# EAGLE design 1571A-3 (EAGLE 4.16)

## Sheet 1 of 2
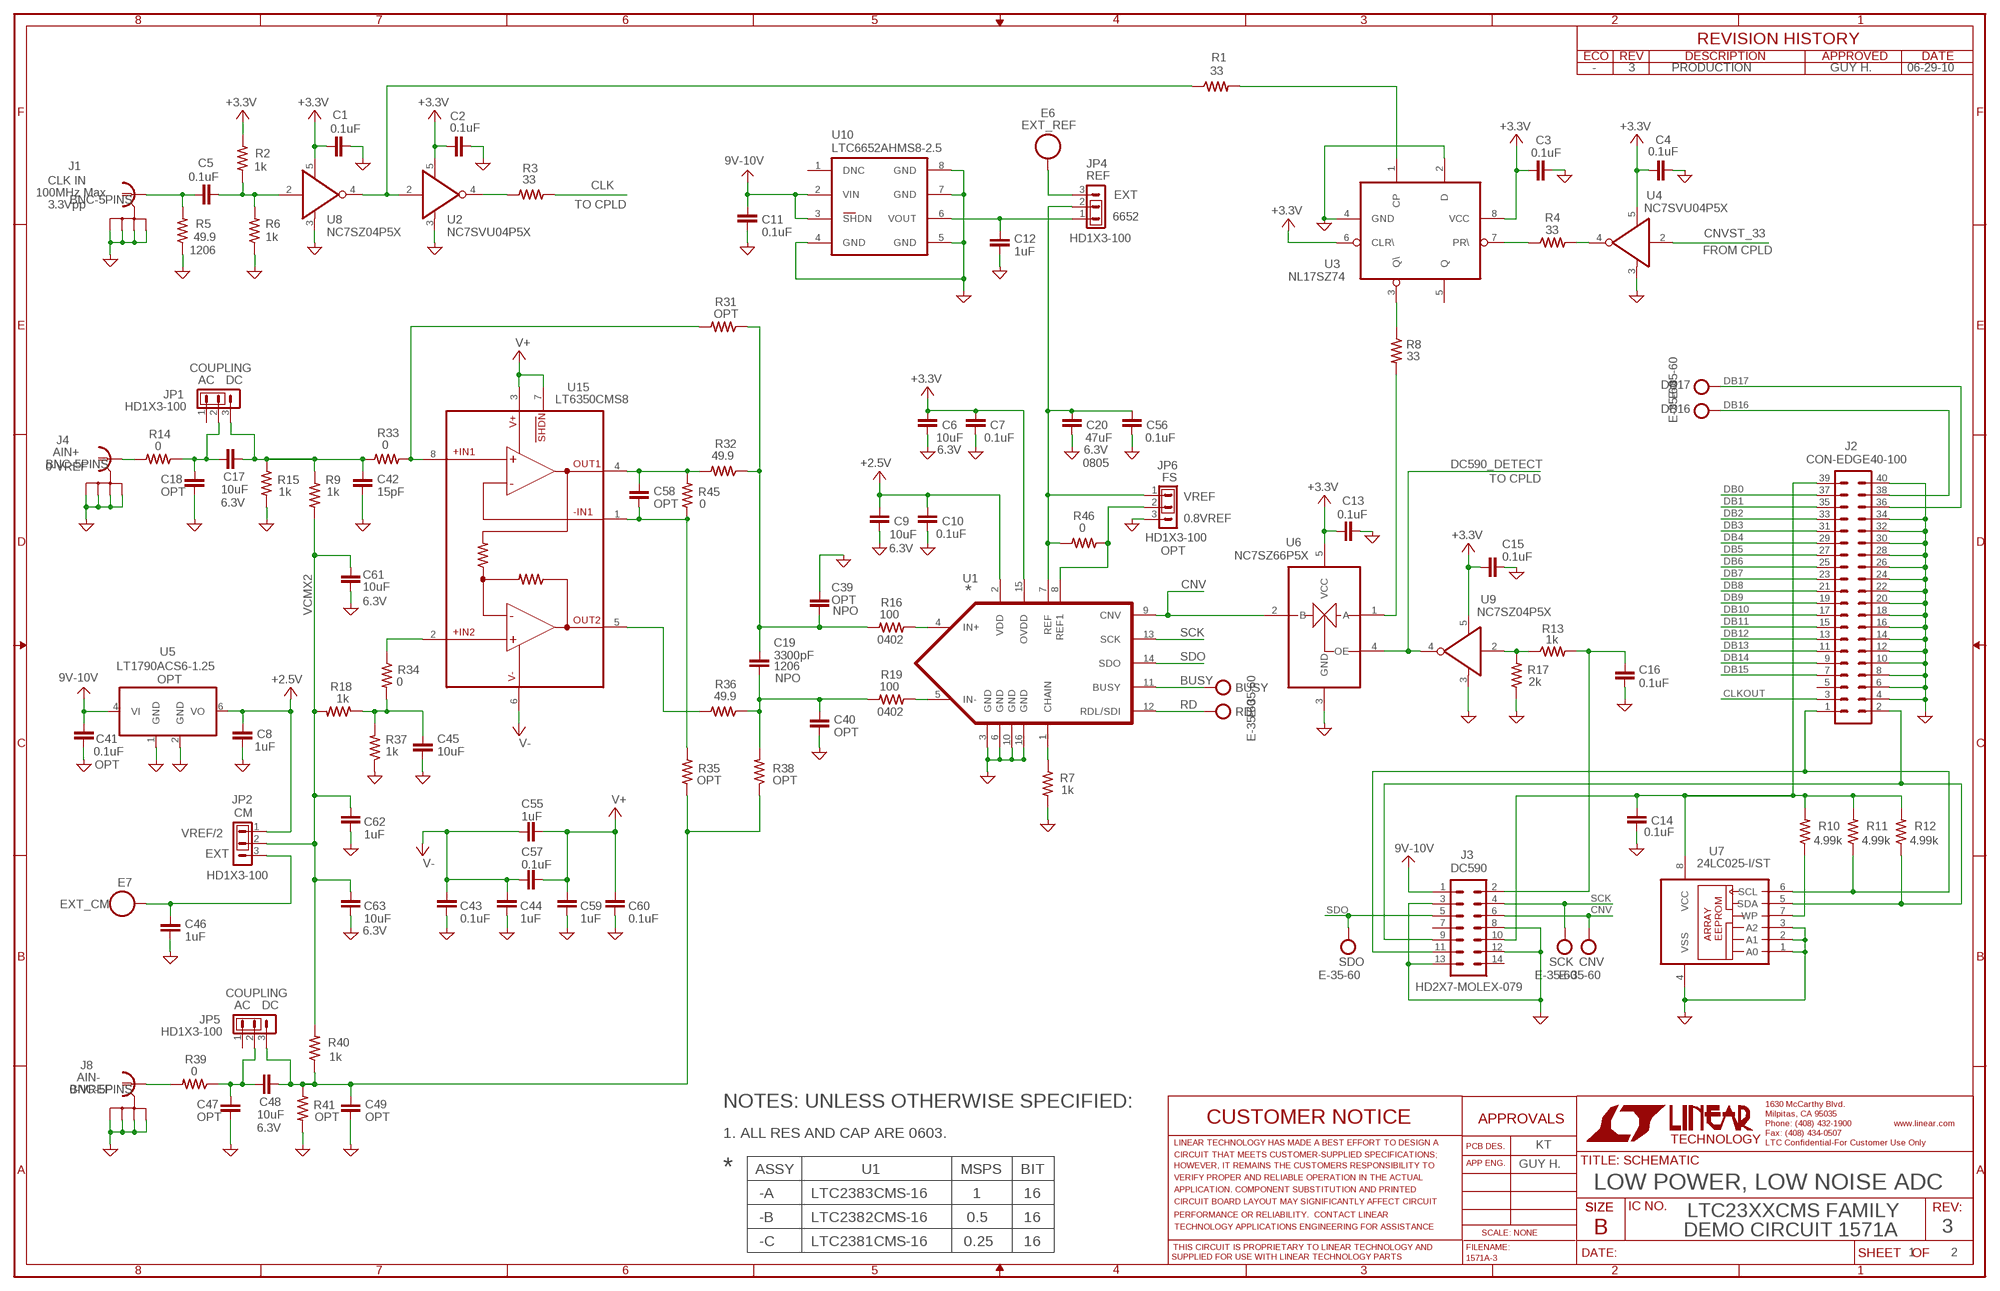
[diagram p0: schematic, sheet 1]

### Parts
BUSY  E-35-60  [PAD-35-60]
C1  0.1uF  CAP-NP-SMT-0603  [0603]
C2  0.1uF  CAP-NP-SMT-0603  [0603]
C3  0.1uF  CAP-NP-SMT-0603  [0603]
C4  0.1uF  CAP-NP-SMT-0603  [0603]
C5  0.1uF  CAP-NP-SMT-0603  [0603]
C6  10uF  CAP-NP-SMT-0603  [0603]
C7  0.1uF  CAP-NP-SMT-0603  [0603]
C8  1uF  CAP-NP-SMT-0603  [0603]
C9  10uF  CAP-NP-SMT-0603  [0603]
C10  0.1uF  CAP-NP-SMT-0603  [0603]
C11  0.1uF  CAP-NP-SMT-0603  [0603]
C12  1uF  CAP-NP-SMT-0603  [0603]
C13  0.1uF  CAP-NP-SMT-0603  [0603]
C14  0.1uF  CAP-NP-SMT-0603  [0603]
C15  0.1uF  CAP-NP-SMT-0603  [0603]
C16  0.1uF  CAP-NP-SMT-0603  [0603]
C17  10uF  CAP-NP-SMT-0603  [0603]
C18  OPT  CAP-NP-SMT-0603  [0603]
C19  3300pF  CAP-NP-SMT-1206  [1206]
C20  47uF  CAP-NP-SMT-0805  [0805]
C39  OPT  CAP-NP-SMT-0603  [0603]
C40  OPT  CAP-NP-SMT-0603  [0603]
C41  0.1uF  CAP-NP-SMT-0603  [0603]
C42  15pF  CAP-NP-SMT-0603  [0603]
C43  0.1uF  CAP-NP-SMT-0603  [0603]
C44  1uF  CAP-NP-SMT-0603  [0603]
C45  10uF  CAP-NP-SMT-0603  [0603]
C46  1uF  CAP-NP-SMT-0603  [0603]
C47  OPT  CAP-NP-SMT-0603  [0603]
C48  10uF  CAP-NP-SMT-0603  [0603]
C49  OPT  CAP-NP-SMT-0603  [0603]
C55  1uF  CAP-NP-SMT-0603  [0603]
C56  0.1uF  CAP-NP-SMT-0603  [0603]
C57  0.1uF  CAP-NP-SMT-0603  [0603]
C58  OPT  CAP-NP-SMT-0603  [0603]
C59  1uF  CAP-NP-SMT-0603  [0603]
C60  0.1uF  CAP-NP-SMT-0603  [0603]
C61  10uF  CAP-NP-SMT-0603  [0603]
C62  1uF  CAP-NP-SMT-0603  [0603]
C63  10uF  CAP-NP-SMT-0603  [0603]
CNV  E-35-60  [PAD-35-60]
DB16  E-35-60  [PAD-35-60]
DB17  E-35-60  [PAD-35-60]
E6  EXT_REF  TP-94-2501-2  [MILLMAX-2501-2]
E7  EXT_CM  TP-94-2501-2  [MILLMAX-2501-2]
J1  BNC-5PINS  [BNC-112404]
J2  CON-EDGE40-100  [CON-EDGE40-100]
J3  HD2X7-MOLEX-079  [HD2X7-079-MOLEX]
J4  BNC-5PINS  [BNC-112404]
J8  BNC-5PINS  [BNC-112404]
JP1  HD1X3-100  [HD1X3-100]
JP2  HD1X3-100  [HD1X3-100]
JP4  HD1X3-100  [HD1X3-100]
JP5  HD1X3-100  [HD1X3-100]
JP6  OPT  HD1X3-100  [HD1X3-100]
R1  33  RES-0603  [0603]
R2  1k  RES-0603  [0603]
R3  33  RES-0603  [0603]
R4  33  RES-0603  [0603]
R5  49.9  RES-1206  [1206]
R6  1k  RES-0603  [0603]
R7  1k  RES-0603  [0603]
R8  33  RES-0603  [0603]
R9  1k  RES-0603  [0603]
R10  4.99k  RES-0603  [0603]
R11  4.99k  RES-0603  [0603]
R12  4.99k  RES-0603  [0603]
R13  1k  RES-0603  [0603]
R14  0  RES-0603  [0603]
R15  1k  RES-0603  [0603]
R16  100  RES-0402  [0402]
R17  2k  RES-0603  [0603]
R18  1k  RES-0603  [0603]
R19  100  RES-0402  [0402]
R31  OPT  RES-0603  [0603]
R32  49.9  RES-0603  [0603]
R33  0  RES-0603  [0603]
R34  0  RES-0603  [0603]
R35  OPT  RES-0603  [0603]
R36  49.9  RES-0603  [0603]
R37  1k  RES-0603  [0603]
R38  OPT  RES-0603  [0603]
R39  0  RES-0603  [0603]
R40  1k  RES-0603  [0603]
R41  OPT  RES-0603  [0603]
R45  0  RES-0603  [0603]
R46  0  RES-0603  [0603]
RD  E-35-60  [PAD-35-60]
SCK  E-35-60  [PAD-35-60]
SDO  E-35-60  [PAD-35-60]
U1  *  LTC238X-16PINS  [MS16]
U2  NC7SVU04P5X  [SC70-5]
U3  NL17SZ74  [US8]
U4  NC7SVU04P5X  NC7ST04P5X  [SC70-5]
U5  LT1790ACS6-1.25  LT1790ACS6-2.048  [SOT23-6]
U6  NC7SZ66P5X  [SC70-5]
U7  24LC025-I/ST  [TSSOP8]
U8  NC7SZ04P5X  [SC70-5]
U9  NC7SZ04P5X  [SC70-5]
U10  LTC6652AHMS8-2.5  [MS8]
U15  LT6350CMS8  [MS8]

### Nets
9V-10V: C11.2 C41.2 J3.1 U5.4(VI) U10.2(VIN) U10.3(SHDN) ; also sheet 2
+2.5V: C8.2 C9.2 C10.2 JP2.1 U1.2(VDD) U5.6(VO) ; also sheet 2
+3.3V: C1.1 C2.1 C3.1 C4.1 C6.2 C7.2 C13.1 C15.2 R2.2 U1.15(OVDD) U2.5(VCC) U3.6(CLR\) U3.8(VCC) U4.5(VCC) U6.5(VCC) U8.5(VCC) U9.5(VCC) ; also sheet 2
BUSY: BUSY.1 U1.11(BUSY) ; also sheet 2
CLK: R3.2 ; also sheet 2
CLKOUT: J2.3 ; also sheet 2
CNV: CNV.1 J3.6 U1.9(CNV) U6.2(B)
CNVST_33: U4.2(A) ; also sheet 2
DB0: J2.37 ; also sheet 2
DB1: J2.35 ; also sheet 2
DB2: J2.33 ; also sheet 2
DB3: J2.31 ; also sheet 2
DB4: J2.29 ; also sheet 2
DB5: J2.27 ; also sheet 2
DB6: J2.25 ; also sheet 2
DB7: J2.23 ; also sheet 2
DB8: J2.21 ; also sheet 2
DB9: J2.19 ; also sheet 2
DB10: J2.17 ; also sheet 2
DB11: J2.15 ; also sheet 2
DB12: J2.13 ; also sheet 2
DB13: J2.11 ; also sheet 2
DB14: J2.9 ; also sheet 2
DB15: J2.7 ; also sheet 2
DB16: DB16.1 J2.38 ; also sheet 2
DB17: DB17.1 J2.36 ; also sheet 2
DC590_DETECT: U6.4(OE) U9.4(Y) ; also sheet 2
DC590VP: C16.1 J3.2 R13.2
GND: C1.2 C2.2 C3.2 C4.2 C6.1 C7.1 C8.1 C9.1 C10.1 C11.1 C12.1 C13.2 C14.2 C15.1 C16.2 C18.2 C20.1 C39.2 C40.2 C41.1 C42.2 C43.2 C44.2 C45.1 C46.1 C47.2 C49.2 C56.1 C59.2 C60.2 C61.2 C62.2 C63.2 J1.2(GND) J1.3(GND) J1.4(GND) J1.5(GND) J2.4 J2.6 J2.8 J2.10 J2.12 J2.14 J2.16 J2.18 J2.20 J2.22 J2.24 J2.26 J2.28 J2.30 J2.32 J2.34 J2.40 J3.3 J3.8 J3.12 J3.13 J4.2(GND) J4.3(GND) J4.4(GND) J4.5(GND) J8.2(GND) J8.3(GND) J8.4(GND) J8.5(GND) JP6.3 R5.1 R6.1 R7.2 R15.2 R17.1 R37.1 R41.2 U1.3(GND) U1.6(GND) U1.10(GND) U1.16(GND) U2.3(GND) U3.2(D) U3.4(GND) U4.3(GND) U5.1(GND) U5.2(GND) U6.3(GND) U7.1(A0) U7.2(A1) U7.3(A2) U7.4(VSS) U8.3(GND) U9.3(GND) U10.4(GND) U10.5(GND) U10.7(GND) U10.8(GND) ; supply symbol labelled - ; also sheet 2
N$1: C17.1 C18.1 JP1.2 R14.1
N$2: J4.1 R14.2
N$7: C20.2 C56.2 JP4.2 JP6.1 R46.1 U1.7(REF)
N$8: C58.1 R32.2 R45.1 U15.4(OUT1)
N$10: E6.1 JP4.3
N$11: R7.1 U1.1(CHAIN)
N$12: R8.1 U3.3(Q\)
N$13: R13.1 R17.2 U9.2(A)
N$15: R16.1 U1.4(IN+)
N$16: R19.1 U1.5(IN-)
N$17: R10.1 U7.7(WP)
N$19: J2.1 J3.11 R11.1 U7.6(SCL)
N$21: C12.2 JP4.1 U10.6(VOUT)
N$22: C19.1 C39.1 R16.2 R31.1 R32.1
N$23: R4.1 U3.7(PR\)
N$24: C46.2 E7.1 JP2.3
N$25: R4.2 U4.4(Y)
N$26: C17.2 C42.1 JP1.3 R9.1 R15.1 R33.2
N$27: C5.1 J1.1 R5.2
N$28: C5.2 R2.1 R6.2 U8.2(A)
N$29: R1.2 U3.1(CP)
N$31: R3.1 U2.4(Y)
N$32: C19.2 C40.1 R19.2 R36.1 R38.2
N$33: R31.2 R33.1 U15.8(+IN1)
N$34: J2.2 J3.9 R12.1 U7.5(SDA)
N$36: R1.1 U2.2(A) U8.4(Y)
N$37: C45.2 R18.1 R34.2 R37.2
N$39: JP6.2 R46.2 U1.8(REF1)
N$40: C58.2 R35.1 R45.2 U15.1(-IN1)
N$41: R8.2 U6.1(A)
N$42: J8.1 R39.2
N$43: R36.2 U15.5(OUT2)
N$44: R34.1 U15.2(+IN2)
N$45: C14.1 J2.39 J3.10 R10.2 R11.2 R12.2 U7.8(VCC)
N$48: C48.2 C49.1 JP5.3 R35.2 R38.1 R40.1 R41.1
N$49: C47.1 C48.1 JP5.2 R39.1
RD: RD.1 U1.12(RDL/SDI) ; also sheet 2
SCK: J3.4 SCK.1 U1.13(SCK) ; also sheet 2
SDO: J3.5 SDO.1 U1.14(SDO) ; also sheet 2
V+: C55.2 C57.2 C59.1 C60.1 U15.3(V+) U15.7(SHDN) ; also sheet 2
V-: C43.1 C44.1 C55.1 C57.1 U15.6(V-) ; also sheet 2
VCMX2: C61.1 C62.1 C63.1 JP2.2 R9.2 R18.2 R40.2
Unconnected: J2.5 J3.7 J3.14 JP1.1 JP5.1 U2.1(NC) U3.5(Q) U4.1(NC) U8.1(NC) U9.1(NC) U10.1(DNC)

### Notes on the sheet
- - | 3 | PRODUCTION | GUY H. | 06-29-10
- REF
- CLK IN
- 100MHz Max | EXT
- 3.3Vpp | TO CPLD
- 6652
- 1206 | FROM CPLD
- COUPLING
- AC | DC
- AIN+ | 6.3V | 6.3V
- 0805
- 0-VREF
- FS | TO CPLD
- VREF
- 6.3V
- 0.8VREF
- HD1X3-100
- 6.3V
- 6.3V
- NPO
- 0402
- 1206
- OPT | NPO
- 0402
- OPT
- CM
- VREF/2
- EXT
- DC590
- 6.3V
- COUPLING
- AC | DC
- AIN-
- 0-VREF
- NOTES: UNLESS OTHERWISE SPECIFIED:
- 6.3V
- 1. ALL RES AND CAP ARE 0603.
- KT
- GUY H.
- * | ASSY | U1 | MSPS | BIT
- LOW POWER, LOW NOISE ADC
- -A | LTC2383CMS-16 | 1 | 16
- LTC23XXCMS FAMILY
- -B | LTC2382CMS-16 | 0.5 | 16
- DEMO CIRCUIT 1571A | 3
- -C | LTC2381CMS-16 | 0.25 | 16
- 1 | 2

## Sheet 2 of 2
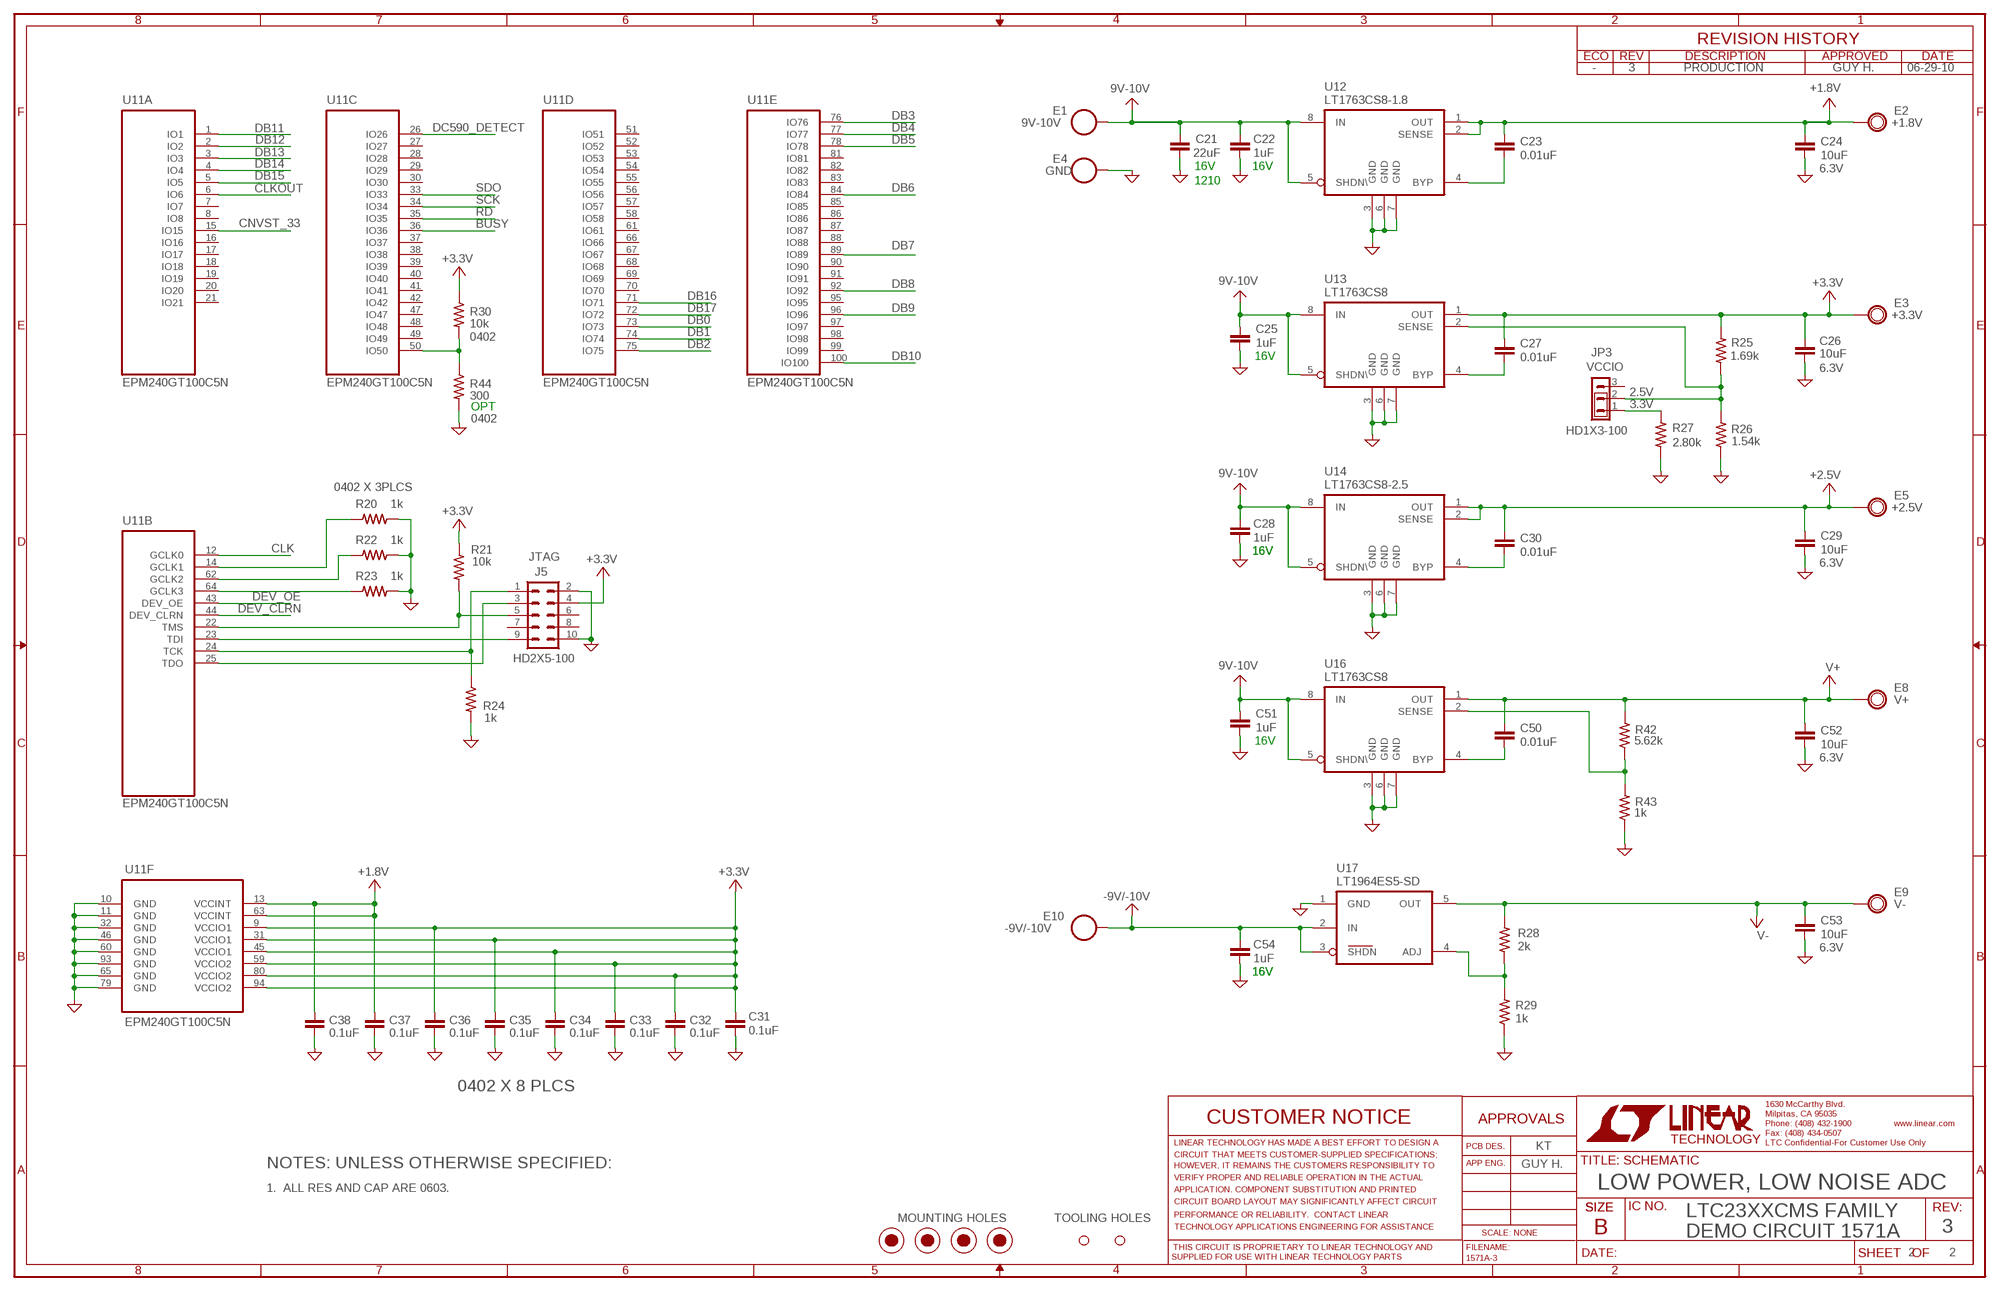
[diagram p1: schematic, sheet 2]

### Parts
C21  22uF  CAP-NP-SMT-1210  [1210]
C22  1uF  CAP-NP-SMT-0603  [0603]
C23  0.01uF  CAP-NP-SMT-0603  [0603]
C24  10uF  CAP-NP-SMT-0603  [0603]
C25  1uF  CAP-NP-SMT-0603  [0603]
C26  10uF  CAP-NP-SMT-0603  [0603]
C27  0.01uF  CAP-NP-SMT-0603  [0603]
C28  1uF  CAP-NP-SMT-0603  [0603]
C29  10uF  CAP-NP-SMT-0603  [0603]
C30  0.01uF  CAP-NP-SMT-0603  [0603]
C31  0.1uF  CAP-NP-SMT-0402  [0402]
C32  0.1uF  CAP-NP-SMT-0402  [0402]
C33  0.1uF  CAP-NP-SMT-0402  [0402]
C34  0.1uF  CAP-NP-SMT-0402  [0402]
C35  0.1uF  CAP-NP-SMT-0402  [0402]
C36  0.1uF  CAP-NP-SMT-0402  [0402]
C37  0.1uF  CAP-NP-SMT-0402  [0402]
C38  0.1uF  CAP-NP-SMT-0402  [0402]
C50  0.01uF  CAP-NP-SMT-0603  [0603]
C51  1uF  CAP-NP-SMT-0603  [0603]
C52  10uF  CAP-NP-SMT-0603  [0603]
C53  10uF  CAP-NP-SMT-0603  [0603]
C54  1uF  CAP-NP-SMT-0603  [0603]
E1  9V-10V  TP-94-2501-2  [MILLMAX-2501-2]
E2  +1.8V  TP-64-2308-2  [MILLMAX-2308-2]
E3  +3.3V  TP-64-2308-2  [MILLMAX-2308-2]
E4  GND  TP-94-2501-2  [MILLMAX-2501-2]
E5  +2.5V  TP-64-2308-2  [MILLMAX-2308-2]
E8  V+  TP-64-2308-2  [MILLMAX-2308-2]
E9  V-  TP-64-2308-2  [MILLMAX-2308-2]
E10  -9V/-10V  TP-94-2501-2  [MILLMAX-2501-2]
J5  HD2X5-100  [HD2X5-100]
JP3  HD1X3-100  [HD1X3-100]
MTG1  MTG-8831-8831  MTG-8831-STANDOFF  [MTG-8831]
MTG2  MTG-8831-8831  MTG-8831-STANDOFF  [MTG-8831]
MTG3  MTG-8831-8831  MTG-8831-STANDOFF  [MTG-8831]
MTG4  MTG-8831-8831  MTG-8831-STANDOFF  [MTG-8831]
R20  1k  RES-0402  [0402]
R21  10k  RES-0603  [0603]
R22  1k  RES-0402  [0402]
R23  1k  RES-0402  [0402]
R24  1k  RES-0603  [0603]
R25  1.69k  RES-0603  [0603]
R26  1.54k  RES-0603  [0603]
R27  2.80k  RES-0603  [0603]
R28  2k  RES-0603  [0603]
R29  1k  RES-0603  [0603]
R30  10k  RES-0402  [0402]
R42  5.62k  RES-0603  [0603]
R43  1k  RES-0603  [0603]
R44  300  RES-0402  [0402]
U11  EPM240GT100C5N  EPM240T-TQFP100  [TQFP100]
U12  LT1763CS8-1.8  LT1763-1.8CS8  [SO8]
U13  LT1763CS8  [SO8]
U14  LT1763CS8-2.5  [SO8]
U16  LT1763CS8  [SO8]
U17  LT1964ES5-SD  LT1964ES5-SDES5  [SOT23-5]
X1  TOOLINGHOLE-70MIL  [TOOLINGHOLE]
X2  TOOLINGHOLE-70MIL  [TOOLINGHOLE]

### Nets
9V-10V: C21.1 C22.1 C25.1 C28.1 C51.1 E1.1 U12.5(SHDN\) U12.8(IN) U13.5(SHDN\) U13.8(IN) U14.5(SHDN\) U14.8(IN) U16.5(SHDN\) U16.8(IN) ; also sheet 1
+1.8V: C23.1 C24.1 C37.1 C38.1 E2.1 U11.13(F:VCCINT) U11.63(F:VCCINT) U12.1(OUT) U12.2(SENSE)
+2.5V: C29.1 C30.1 E5.1 U14.1(OUT) U14.2(SENSE) ; also sheet 1
+3.3V: C26.1 C27.1 C31.1 C32.1 C33.1 C34.1 C35.1 C36.1 E3.1 J5.4 R21.1 R25.2 R30.1 U11.9(F:VCCIO1) U11.31(F:VCCIO1) U11.45(F:VCCIO1) U11.59(F:VCCIO2) U11.80(F:VCCIO2) U11.94(F:VCCIO2) U13.1(OUT) ; also sheet 1
-9V/-10V: C54.1 E10.1 U17.2(IN) U17.3(SHDN)
BUSY: U11.36(C:IO36) ; also sheet 1
CLK: U11.12(B:GCLK0) ; also sheet 1
CLKOUT: U11.6(A:IO6) ; also sheet 1
CNVST_33: U11.15(A:IO15) ; also sheet 1
DB0: U11.73(D:IO73) ; also sheet 1
DB1: U11.74(D:IO74) ; also sheet 1
DB2: U11.75(D:IO75) ; also sheet 1
DB3: U11.76(E:IO76) ; also sheet 1
DB4: U11.77(E:IO77) ; also sheet 1
DB5: U11.78(E:IO78) ; also sheet 1
DB6: U11.84(E:IO84) ; also sheet 1
DB7: U11.89(E:IO89) ; also sheet 1
DB8: U11.92(E:IO92) ; also sheet 1
DB9: U11.96(E:IO96) ; also sheet 1
DB10: U11.100(E:IO100) ; also sheet 1
DB11: U11.1(A:IO1) ; also sheet 1
DB12: U11.2(A:IO2) ; also sheet 1
DB13: U11.3(A:IO3) ; also sheet 1
DB14: U11.4(A:IO4) ; also sheet 1
DB15: U11.5(A:IO5) ; also sheet 1
DB16: U11.71(D:IO71) ; also sheet 1
DB17: U11.72(D:IO72) ; also sheet 1
DC590_DETECT: U11.26(C:IO26) ; also sheet 1
DEV_CLRN: U11.44(B:DEV_CLRN)
DEV_OE: U11.43(B:DEV_OE)
GND: C21.2 C22.2 C24.2 C25.2 C26.2 C28.2 C29.2 C31.2 C32.2 C33.2 C34.2 C35.2 C36.2 C37.2 C38.2 C51.2 C52.2 C53.2 C54.2 E4.1 J5.2 J5.10 R20.1 R22.1 R23.1 R24.2 R26.1 R27.1 R29.1 R43.1 R44.2 U11.10(F:GND) U11.11(F:GND) U11.32(F:GND) U11.46(F:GND) U11.60(F:GND) U11.65(F:GND) U11.79(F:GND) U11.93(F:GND) U12.3(GND) U12.6(GND) U12.7(GND) U13.3(GND) U13.6(GND) U13.7(GND) U14.3(GND) U14.6(GND) U14.7(GND) U16.3(GND) U16.6(GND) U16.7(GND) U17.1(GND) ; also sheet 1
N$3: J5.9 U11.23(B:TDI)
N$4: J5.1 R24.1 U11.24(B:TCK)
N$5: J5.3 U11.25(B:TDO)
N$6: J5.5 R21.2 U11.22(B:TMS)
N$9: R23.2 U11.64(B:GCLK3)
N$14: JP3.1 R27.2
N$18: R42.1 R43.2 U16.2(SENSE)
N$20: R28.1 R29.2 U17.4(ADJ)
N$30: R22.2 U11.62(B:GCLK2)
N$38: JP3.2 R25.1 R26.2 U13.2(SENSE)
N$50: C27.2 U13.4(BYP)
N$51: R20.2 U11.14(B:GCLK1)
N$52: R30.2 R44.1 U11.50(C:IO50)
N$53: C23.2 U12.4(BYP)
N$54: C50.2 U16.4(BYP)
N$57: C30.2 U14.4(BYP)
RD: U11.35(C:IO35) ; also sheet 1
SCK: U11.34(C:IO34) ; also sheet 1
SDO: U11.33(C:IO33) ; also sheet 1
V+: C50.1 C52.1 E8.1 R42.2 U16.1(OUT) ; also sheet 1
V-: C53.1 E9.1 R28.2 U17.5(OUT) ; also sheet 1
Unconnected: J5.6 J5.7 J5.8 JP3.3 MTG1.1 MTG2.1 MTG3.1 MTG4.1 U11.7(A:IO7) U11.8(A:IO8) U11.16(A:IO16) U11.17(A:IO17) U11.18(A:IO18) U11.19(A:IO19) U11.20(A:IO20) U11.21(A:IO21) U11.27(C:IO27) U11.28(C:IO28) U11.29(C:IO29) U11.30(C:IO30) U11.37(C:IO37) U11.38(C:IO38) U11.39(C:IO39) U11.40(C:IO40) U11.41(C:IO41) U11.42(C:IO42) U11.47(C:IO47) U11.48(C:IO48) U11.49(C:IO49) U11.51(D:IO51) U11.52(D:IO52) U11.53(D:IO53) U11.54(D:IO54) U11.55(D:IO55) U11.56(D:IO56) U11.57(D:IO57) U11.58(D:IO58) U11.61(D:IO61) U11.66(D:IO66) U11.67(D:IO67) U11.68(D:IO68) U11.69(D:IO69) U11.70(D:IO70) U11.81(E:IO81) U11.82(E:IO82) U11.83(E:IO83) U11.85(E:IO85) U11.86(E:IO86) U11.87(E:IO87) U11.88(E:IO88) U11.90(E:IO90) U11.91(E:IO91) U11.95(E:IO95) U11.97(E:IO97) U11.98(E:IO98) U11.99(E:IO99) X1.1 X2.1

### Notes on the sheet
- - | 3 | PRODUCTION | GUY H. | 06-29-10
- 16V | 16V | 6.3V
- 1210
- 0402
- 16V
- VCCIO | 6.3V
- 2.5V
- OPT | 3.3V
- 0402
- 0402 X 3PLCS
- 16V | 16V
- JTAG
- 6.3V
- 16V
- 6.3V
- 6.3V
- 16V | 16V
- 0402 X 8 PLCS
- KT
- NOTES: UNLESS OTHERWISE SPECIFIED: | GUY H.
- 1.  ALL RES AND CAP ARE 0603. | LOW POWER, LOW NOISE ADC
- LTC23XXCMS FAMILY
- MOUNTING HOLES | TOOLING HOLES
- DEMO CIRCUIT 1571A | 3
- 2 | 2

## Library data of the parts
BUSY CNV DB16 DB17 RD SCK SDO = LTDB_Connectors:E-35-60
C1-C63 = LTDB_Passives:CAP-NP-SMT-: Capacitor; Non-polar; SMT
E1 E4 E6 E7 E10 = EagleLib:TP-94
E2 E3 E5 E8 E9 = EagleLib:TP-64
J1 J4 J8 = LTDB_Connectors:BNC-5PINS: BNC CONNECTOR M/A COM www.macom.com distributor Farnell 149-452
J2 = EagleLib:CON-EDGE40-100
J3 = LTDB_Connectors:HD2X7-MOLEX: HDR-7x2-Pin-Straight-Shrouded Molex 87331-1420
J5 = EagleLib:HD2X5
JP1-JP6 = LTDB_Connectors:HD1X3: Jumper,3pin, point connections
MTG1-MTG4 = LTDB_Connectors:MTG-8831
R1-R46 = LTDB_Passives:RES-: Resistor; GP
U1 = EagleLib:LTC238X-16PINS
U2 = LTDB_ICs:NC7SVU04
U3 = LTDB_ICs:NL17SZ74
U4 = LTDB_ICs:NC7ST04
U5 = LTDB_Linear_Parts:LT1790?-*: Micropower SOT-23 Low Dropout Reference Family
U6 = LTDB_ICs:NC7SZ66
U7 = LTDB_ICs:24LC025
U8 U9 = LTDB_ICs:NC7SZ04
U10 = EagleLib:LTC6652
U11 = LTDB_ICs:EPM240T-TQFP100
U12-U14 U16 = LTDB_Linear_Parts:LT1763: 500MA, Low Noise, LDO Micropwer Regulator
U15 = EagleLib:LT6350
U17 = EagleLib:LT1964ES5-SD
X1 X2 = LTDB_Connectors:TOOLINGHOLE

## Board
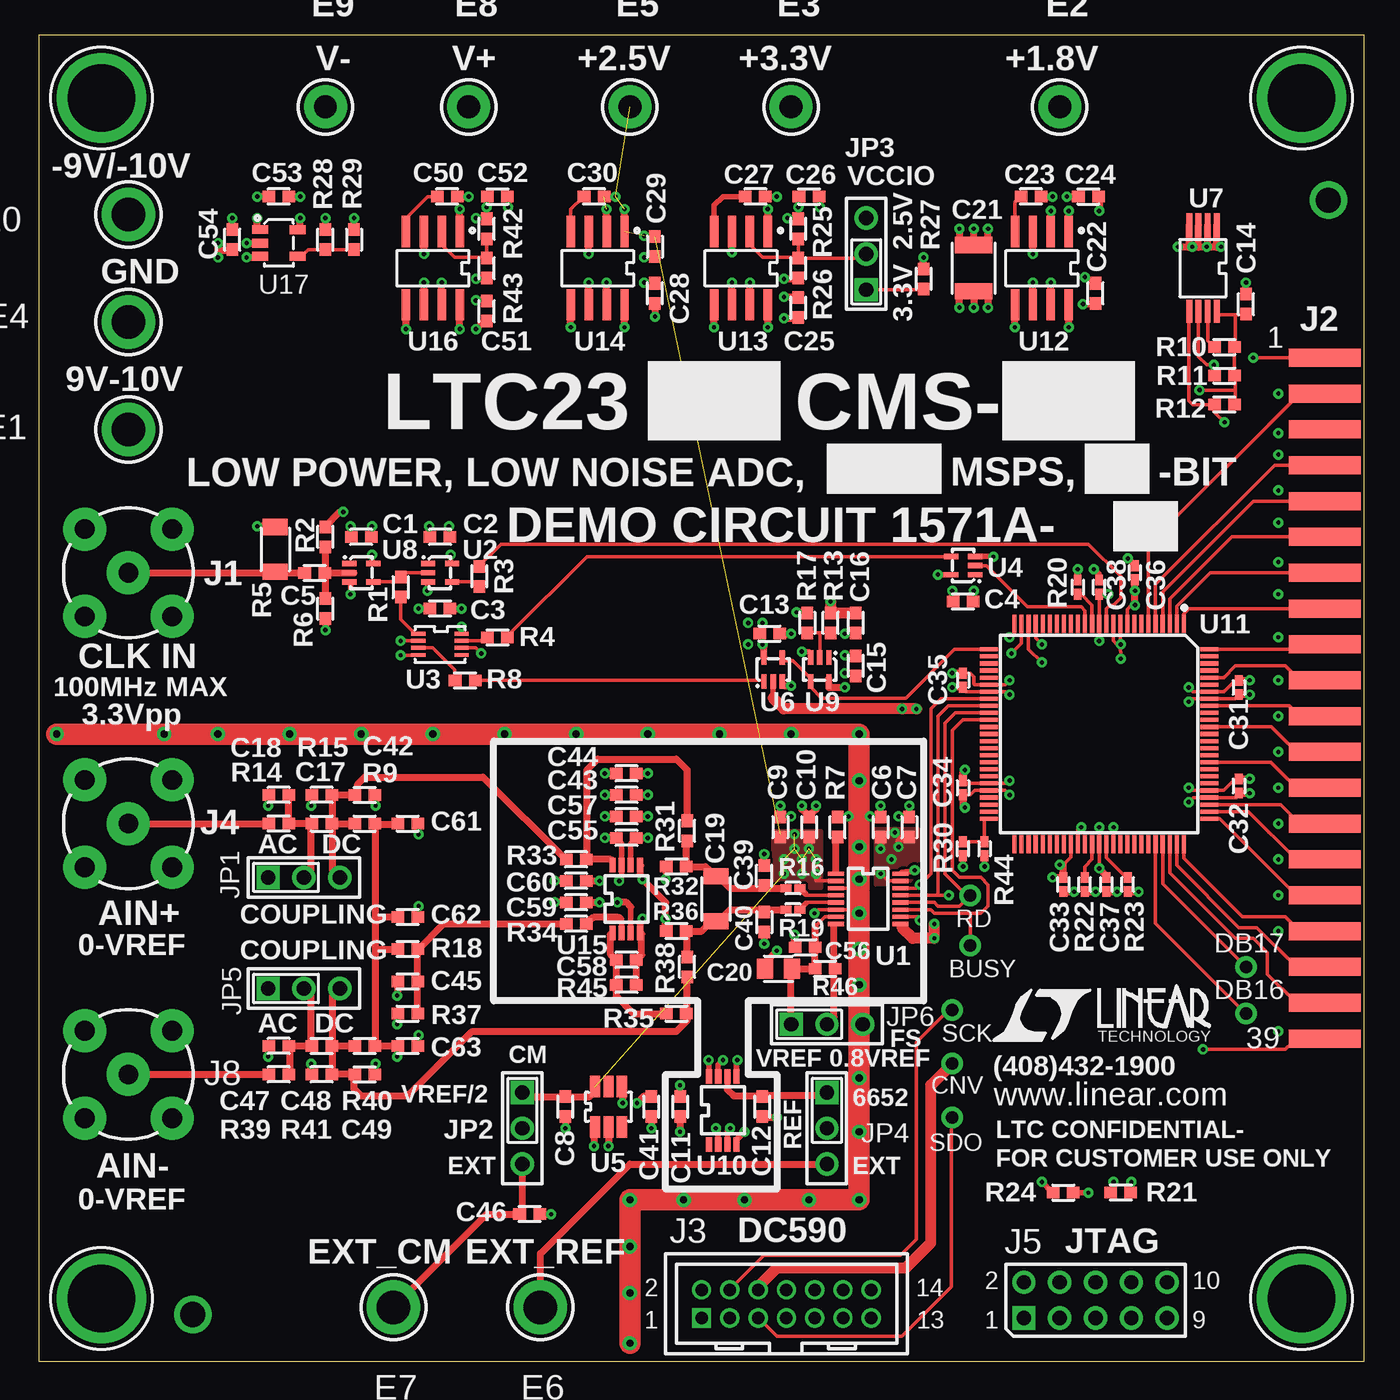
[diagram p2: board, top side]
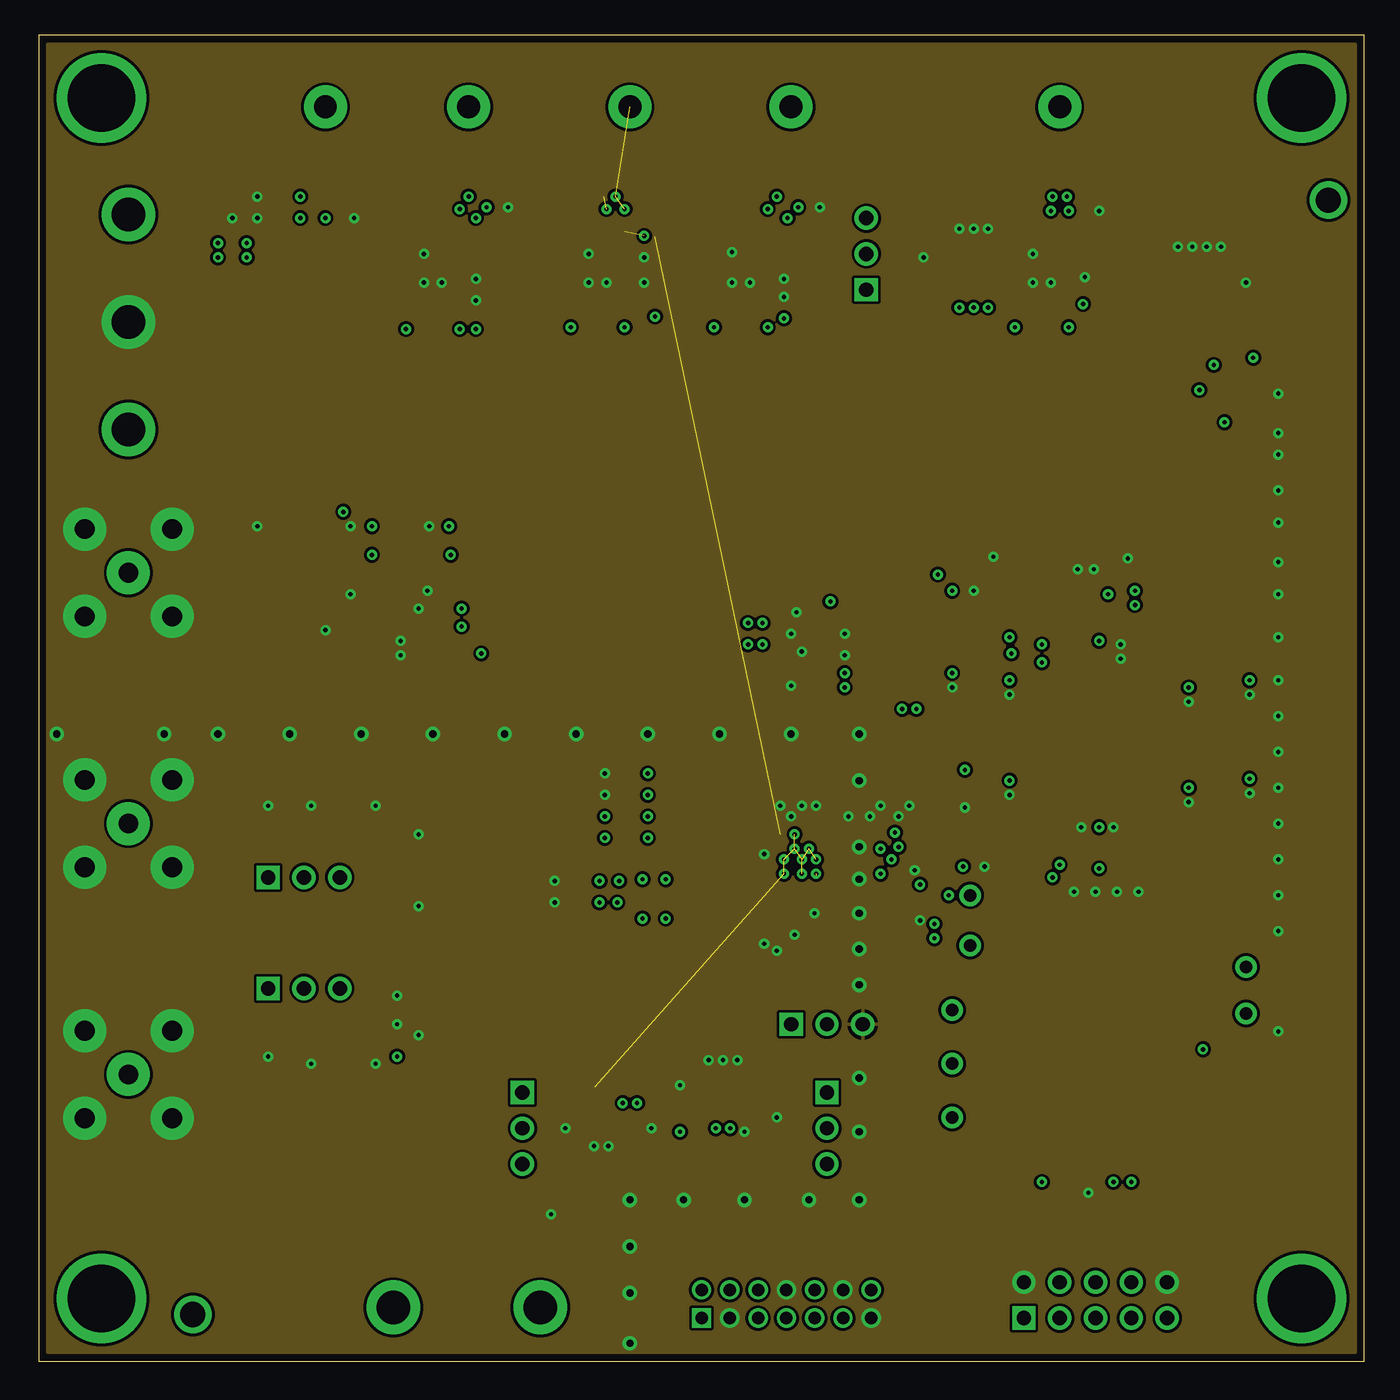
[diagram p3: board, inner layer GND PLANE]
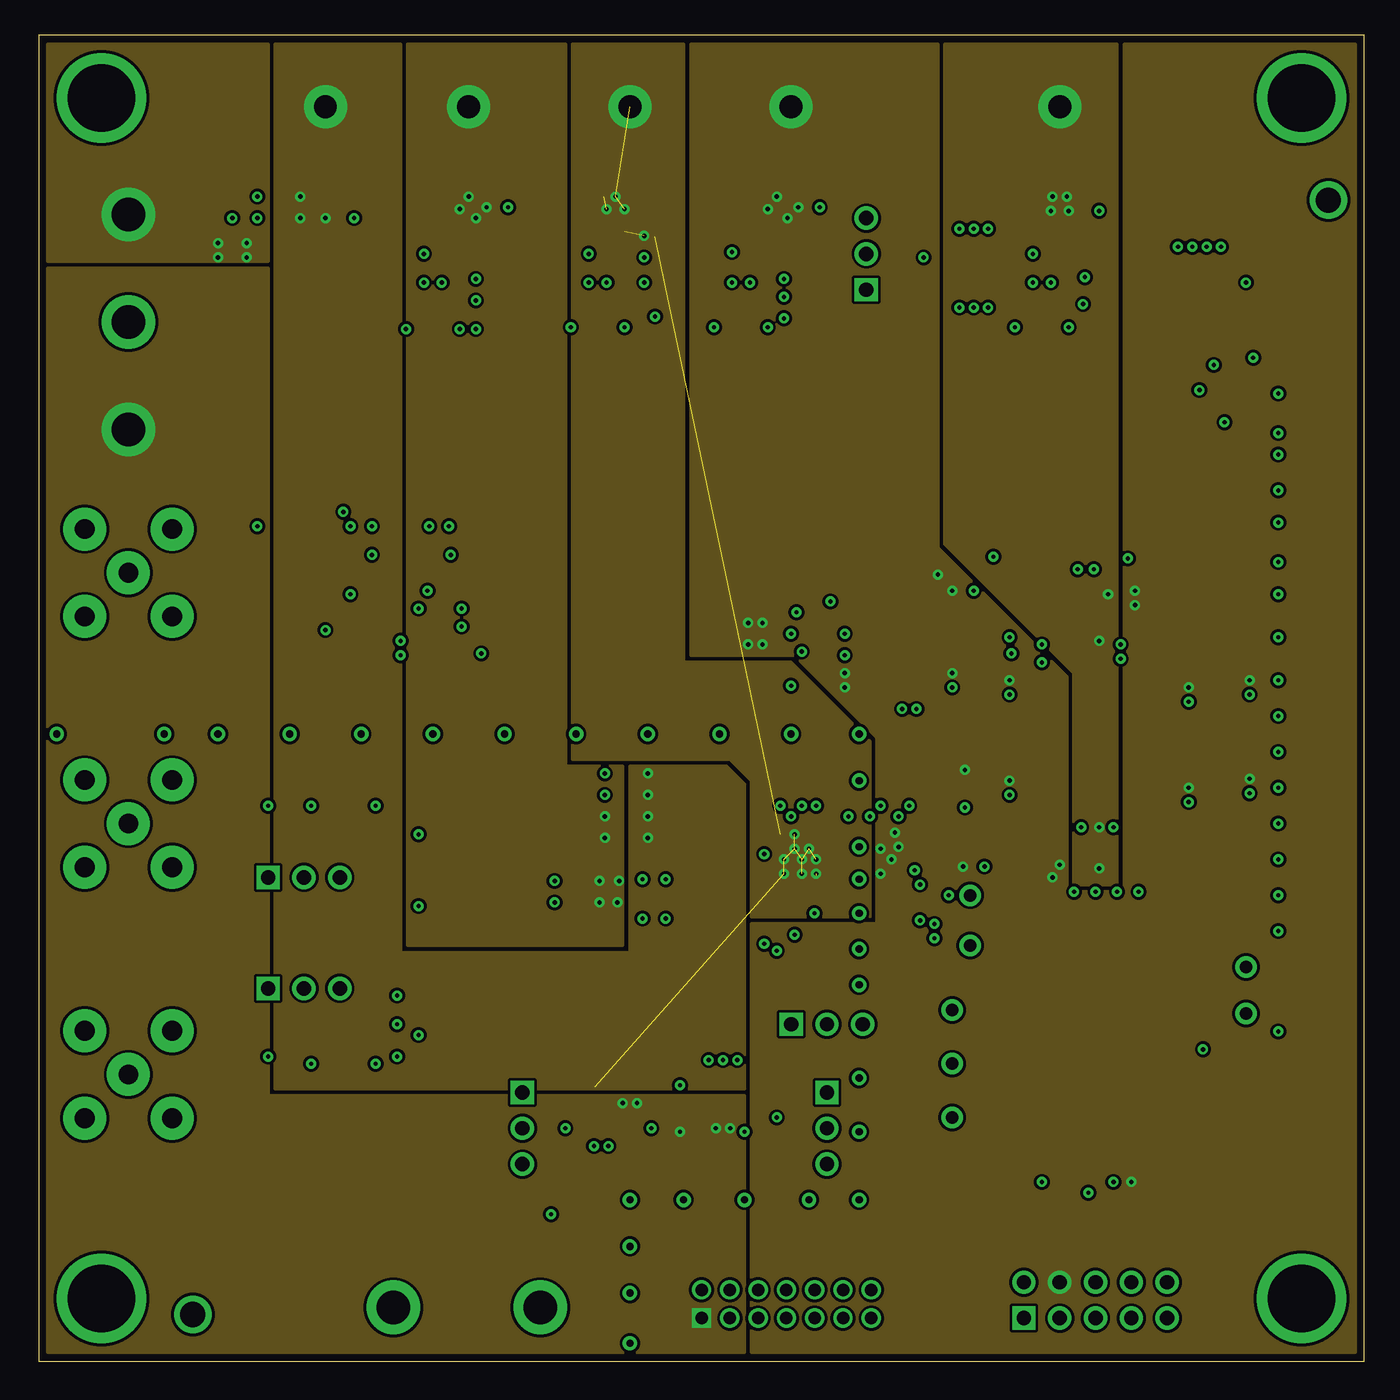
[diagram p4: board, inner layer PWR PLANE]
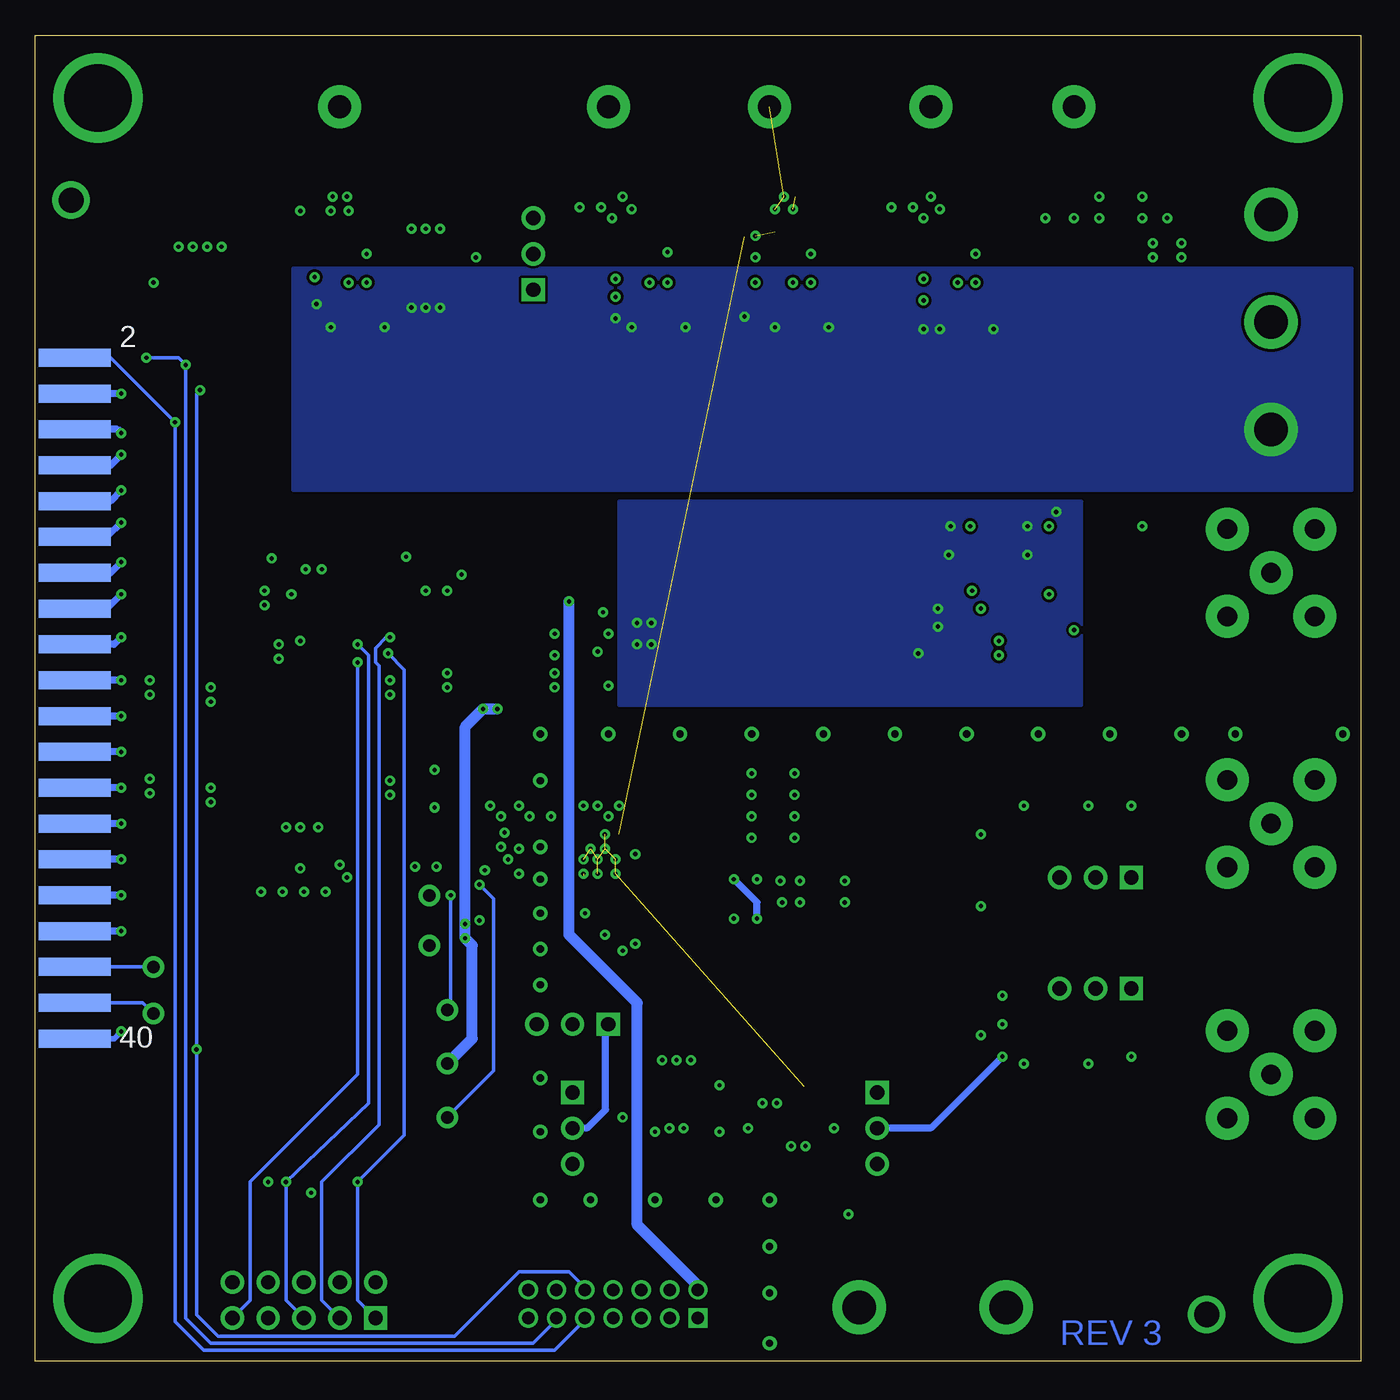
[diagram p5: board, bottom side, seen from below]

Size 93.98 x 93.98 mm. Coordinates in mm from the lower left corner, seen from the top.
Outline: 0,0 93.98,0 93.98,93.98 0,93.98 0,0
Copper layers (1*2+3*16): TOP 0.0508mm / dielectric 0.4318mm / GND PLANE 0.0254mm / dielectric 0.7112mm / PWR PLANE 0.0254mm / dielectric 0.3048mm / BOTTOM 0.0508mm
Design rules "Kim-Design Rules": minimum track width 10mil, minimum drill 12mil, track to track 8mil, track to pad 8mil, pad to pad 8mil, via to via 8mil, smd to smd 0mil, copper to edge 10mil, drill to drill 10mil, minimum pad ring 8mil, minimum via ring 8mil, stop-mask expansion 4mil, vias tented up to drill 15mil, thermal gap 10mil

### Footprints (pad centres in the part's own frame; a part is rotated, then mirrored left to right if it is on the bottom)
PAD-35-60 = drill 0.889 pad 1.524 round: 1 0,0
0603 = smd 0.889 x 0.813: 1 -0.71,0; 2 0.71,0
1206 = smd 1.143 x 1.778: 1 -1.591,0; 2 1.591,0
0805 = smd 1.143 x 1.397: 1 -0.952,0; 2 0.952,0
1210 = smd 1.143 x 2.667: 1 -1.641,0; 2 1.641,0
0402 = smd 0.762 x 0.559: 1 -0.498,0; 2 0.498,0
MILLMAX-2501-2 = drill 2.388 pad 3.81 round: 1 0,0
MILLMAX-2308-2 = drill 1.626 pad 3.048 round: 1 0,0
BNC-112404 = drill 1.397 pad 3.048 round: 1 0,0; 2 3.099,3.099; 3 -3.099,3.099; 4 -3.099,-3.099; 5 3.099,-3.099
CON-EDGE40-100 = smd 5.08 x 1.27: 1 0,24.13; 3 0,21.59; 5 0,19.05; 7 0,16.51; 9 0,13.97; 11 0,11.43; 13 0,8.89; 15 0,6.35; 17 0,3.81; 19 0,1.27; 21 0,-1.27; 23 0,-3.81; 25 0,-6.35; 27 0,-8.89; 29 0,-11.43; 31 0,-13.97; 33 0,-16.51; 35 0,-19.05; 37 0,-21.59; 39 0,-24.13 | smd 5.08 x 1.27 bottom: 2 0,24.13; 4 0,21.59; 6 0,19.05; 8 0,16.51; 10 0,13.97; 12 0,11.43; 14 0,8.89; 16 0,6.35; 18 0,3.81; 20 0,1.27; 22 0,-1.27; 24 0,-3.81; 26 0,-6.35; 28 0,-8.89; 30 0,-11.43; 32 0,-13.97; 34 0,-16.51; 36 0,-19.05; 38 0,-21.59; 40 0,-24.13
HD2X7-079-MOLEX = drill 0.889 pad 1.372 square: 1 0,0 | drill 0.889 pad 1.372 round: 2 0,2.007; 3 2.007,0; 4 2.007,2.007; 5 4.013,0; 6 4.013,2.007; 7 6.02,0; 8 6.02,2.007; 9 8.026,0; 10 8.026,2.007; 11 10.033,0; 12 10.033,2.007; 13 12.04,0; 14 12.04,2.007
HD2X5-100 = drill 1.016 pad 1.651 square: 1 0,0 | drill 1.016 pad 1.651 round: 2 0,2.54; 3 2.54,0; 4 2.54,2.54; 5 5.08,0; 6 5.08,2.54; 7 7.62,0; 8 7.62,2.54; 9 10.16,0; 10 10.16,2.54
HD1X3-100 = drill 1.016 pad 1.651 square: 1 0,0 | drill 1.016 pad 1.651 round: 2 2.54,0; 3 5.08,0
MTG-8831 = drill 4.775 pad 6.35 round: 1 0,0
MS16 = smd 0.292 x 1.143: 1 -1.778,-2.286; 2 -1.27,-2.286; 3 -0.762,-2.286; 4 -0.254,-2.286; 5 0.254,-2.286; 6 0.762,-2.286; 7 1.27,-2.286; 8 1.778,-2.286; 9 1.778,2.286; 10 1.27,2.286; 11 0.762,2.286; 12 0.254,2.286; 13 -0.254,2.286; 14 -0.762,2.286; 15 -1.27,2.286; 16 -1.778,2.286
SC70-5 = smd 0.381 x 1.016: 1 -0.65,-0.85; 2 0,-0.85; 3 0.65,-0.85; 4 0.65,0.85; 5 -0.65,0.85
US8 = smd 0.279 x 1.016: 1 -0.75,-1.527; 2 -0.25,-1.527; 3 0.25,-1.527; 4 0.75,-1.527; 5 0.75,1.527; 6 0.25,1.527; 7 -0.25,1.527; 8 -0.75,1.527
SOT23-6 = smd 0.711 x 1.524: 1 -0.95,-1.427; 2 0,-1.427; 3 0.95,-1.427; 4 0.95,1.427; 5 0,1.427; 6 -0.95,1.427
TSSOP8 = smd 0.406 x 1.651: 1 -0.975,-3.052; 2 -0.325,-3.052; 3 0.325,-3.052; 4 0.975,-3.052; 5 0.975,3.052; 6 0.325,3.052; 7 -0.325,3.052; 8 -0.975,3.052
MS8 = smd 0.432 x 1.016: 1 -0.99,-2.422; 2 -0.34,-2.422; 3 0.31,-2.422; 4 0.96,-2.422; 5 0.96,2.402; 6 0.31,2.402; 7 -0.34,2.402; 8 -0.99,2.402
TQFP100 = smd 1.27 x 0.292: 1 -7.822,6; 2 -7.822,5.5; 3 -7.822,5; 4 -7.822,4.5; 5 -7.822,4; 6 -7.822,3.5; 7 -7.822,3; 8 -7.822,2.5; 9 -7.822,2; 10 -7.822,1.5; 11 -7.822,1; 12 -7.822,0.5; 13 -7.822,0; 14 -7.822,-0.5; 15 -7.822,-1; 16 -7.822,-1.5; 17 -7.822,-2; 18 -7.822,-2.5; 19 -7.822,-3; 20 -7.822,-3.5; 21 -7.822,-4; 22 -7.822,-4.5; 23 -7.822,-5; 24 -7.822,-5.5; 25 -7.822,-6; 51 7.822,-6; 52 7.822,-5.5; 53 7.822,-5; 54 7.822,-4.5; 55 7.822,-4; 56 7.822,-3.5; 57 7.822,-3; 58 7.822,-2.5; 59 7.822,-2; 60 7.822,-1.5; 61 7.822,-1; 62 7.822,-0.5; 63 7.822,0; 64 7.822,0.5; 65 7.822,1; 66 7.822,1.5; 67 7.822,2; 68 7.822,2.5; 69 7.822,3; 70 7.822,3.5; 71 7.822,4; 72 7.822,4.5; 73 7.822,5; 74 7.822,5.5; 75 7.822,6 | smd 0.292 x 1.27: 26 -6,-7.822; 27 -5.5,-7.822; 28 -5,-7.822; 29 -4.5,-7.822; 30 -4,-7.822; 31 -3.5,-7.822; 32 -3,-7.822; 33 -2.5,-7.822; 34 -2,-7.822; 35 -1.5,-7.822; 36 -1,-7.822; 37 -0.5,-7.822; 38 0,-7.822; 39 0.5,-7.822; 40 1,-7.822; 41 1.5,-7.822; 42 2,-7.822; 43 2.5,-7.822; 44 3,-7.822; 45 3.5,-7.822; 46 4,-7.822; 47 4.5,-7.822; 48 5,-7.822; 49 5.5,-7.822; 50 6,-7.822; 76 6,7.822; 77 5.5,7.822; 78 5,7.822; 79 4.5,7.822; 80 4,7.822; 81 3.5,7.822; 82 3,7.822; 83 2.5,7.822; 84 2,7.822; 85 1.5,7.822; 86 1,7.822; 87 0.5,7.822; 88 0,7.822; 89 -0.5,7.822; 90 -1,7.822; 91 -1.5,7.822; 92 -2,7.822; 93 -2.5,7.822; 94 -3,7.822; 95 -3.5,7.822; 96 -4,7.822; 97 -4.5,7.822; 98 -5,7.822; 99 -5.5,7.822; 100 -6,7.822
SO8 = smd 0.6 x 2.2: 1 -1.905,-2.6; 2 -0.635,-2.6; 3 0.635,-2.6; 4 1.905,-2.6; 5 1.905,2.6; 6 0.635,2.6; 7 -0.635,2.6; 8 -1.905,2.6
SOT23-5 = smd 0.635 x 1.143: 1 -0.965,-1.333; 2 0,-1.333; 3 0.94,-1.333; 4 0.94,1.333; 5 -0.94,1.333
TOOLINGHOLE = drill 1.778 pad 1.778 round: 1 0,0

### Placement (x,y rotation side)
BUSY  66.04,29.46 0 top
C1  22.86,58.42 180 top
C2  28.45,58.42 180 top
C3  28.45,53.34 180 top
C4  65.53,53.85 0 top
C5  19.56,55.88 0 top
C6  59.69,37.85 270 top
C7  61.72,37.85 270 top
C8  37.34,18.03 90 top
C9  52.58,37.85 270 top
C10  54.61,37.85 270 top
C11  45.47,18.03 270 top
C12  51.31,18.03 90 top
C13  51.82,51.56 0 top
C14  85.6,74.93 90 top
C15  57.91,49.28 270 top
C16  57.91,52.32 270 top
C17  20.07,38.1 0 top
C18  17.02,40.13 180 top
C19  48.01,32.77 270 top
C20  52.45,27.81 0 top
C21  66.29,77.47 90 top
C22  74.93,75.69 90 top
C23  70.36,82.55 180 top
C24  74.42,82.55 0 top
C25  53.85,74.68 90 top
C26  54.61,82.55 0 top
C27  50.8,82.55 180 top
C28  43.69,75.69 90 top
C29  43.69,78.99 270 top
C30  39.37,82.55 180 top
C31  85.09,47.75 270 top
C32  85.09,40.77 270 top
C33  72.64,33.78 270 top
C34  65.53,40.64 270 top
C35  65.53,48.26 270 top
C36  77.72,55.88 90 top
C37  75.69,33.78 270 top
C38  75.18,54.86 90 top
C39  51.44,34.42 90 top
C40  51.44,31.11 270 top
C41  43.43,18.03 90 top
C42  23.11,40.13 0 top
C43  41.66,40.13 180 top
C44  41.66,41.66 180 top
C45  26.16,26.92 0 top
C46  34.8,10.41 180 top
C47  17.02,22.35 180 top
C48  20.07,22.35 0 top
C49  23.11,20.32 0 top
C50  28.96,82.55 180 top
C51  31.75,74.42 90 top
C52  32.51,82.55 0 top
C53  17.02,82.55 180 top
C54  13.72,79.5 90 top
C55  41.66,37.08 180 top
C56  54.36,29.34 0 top
C57  41.66,38.61 180 top
C58  41.66,28.45 180 top
C59  38.1,32.51 180 top
C60  38.1,34.04 180 top
C61  26.16,38.1 0 top
C62  26.16,31.5 0 top
C63  26.16,22.35 0 top
CNV  64.77,21.08 0 top
DB16  85.6,24.64 0 top
DB17  85.6,27.94 0 top
E1  6.35,66.04 0 top
E2  72.39,88.9 0 top
E3  53.34,88.9 0 top
E4  6.35,73.66 0 top
E5  41.91,88.9 0 top
E6  35.56,3.81 0 top
E7  25.15,3.81 0 top
E8  30.48,88.9 0 top
E9  20.32,88.9 0 top
E10  6.35,81.28 0 top
J1  6.35,55.88 0 top
J2  91.19,46.99 0 top
J3  46.99,3.05 0 top
J4  6.35,38.1 0 top
J5  69.85,3.05 0 top
J8  6.35,20.32 0 top
JP1  16.26,34.29 0 top
JP2  34.29,19.05 270 top
JP3  58.67,75.95 90 top
JP4  55.88,19.05 270 top
JP5  16.26,26.42 0 top
JP6  53.34,23.88 0 top
MTG1  4.45,4.44 0 top
MTG2  89.54,4.44 0 top
MTG3  89.54,89.53 0 top
MTG4  4.45,89.53 0 top
R1  25.65,54.86 270 top
R2  20.32,58.42 90 top
R3  31.24,55.63 90 top
R4  32.51,51.31 0 top
R5  16.76,57.53 270 top
R6  20.32,53.34 90 top
R7  56.64,37.85 90 top
R8  30.23,48.26 0 top
R9  23.11,38.1 0 top
R10  84.07,71.88 0 top
R11  84.07,69.85 0 top
R12  84.07,67.82 0 top
R13  56.13,52.32 90 top
R14  17.02,38.1 180 top
R15  20.07,40.13 180 top
R16  53.47,33.53 180 top
R17  54.48,52.32 270 top
R18  26.16,29.21 180 top
R19  53.47,32 180 top
R20  73.66,54.86 270 top
R21  76.71,11.94 180 top
R22  74.17,33.78 90 top
R23  77.22,33.78 90 top
R24  72.64,11.94 0 top
R25  53.85,80.26 90 top
R26  53.85,77.47 90 top
R27  62.74,76.71 270 top
R28  20.32,79.5 90 top
R29  22.35,79.5 270 top
R30  65.53,36.32 90 top
R31  45.97,37.59 90 top
R32  45.21,35.05 180 top
R33  38.1,35.56 180 top
R34  38.1,30.99 180 top
R35  45.21,24.64 0 top
R36  45.21,30.48 180 top
R37  26.16,24.64 0 top
R38  45.97,27.94 90 top
R39  17.02,20.32 180 top
R40  23.11,22.35 0 top
R41  20.07,20.32 180 top
R42  31.75,80.26 90 top
R43  31.75,77.47 90 top
R44  67.06,36.32 270 top
R45  41.66,26.67 180 top
R46  55.75,27.81 0 top
RD  66.04,33.02 0 top
SCK  64.77,24.89 0 top
SDO  64.77,17.27 0 top
U1  58.8,32.77 270 top
U2  28.45,55.88 270 top
U3  28.45,50.8 270 top
U4  65.53,56.39 90 top
U5  40.39,18.03 0 top
U6  52.07,49.02 0 top
U7  82.55,77.47 180 top
U8  22.86,55.88 270 top
U9  55.37,49.02 180 top
U10  48.51,17.78 0 top
U11  75.18,44.45 270 top
U12  71.12,77.47 180 top
U13  49.78,77.47 180 top
U14  39.62,77.47 180 top
U15  41.66,32.77 0 top
U16  27.94,77.47 180 top
U17  17.02,79.25 270 top
U$1  [TITLEBLK-REV]  not placed on the board
U$2  [4-LAYER-NAME]  not placed on the board
U$3  [LT-LOGO]  66.93,22.35 0 top
X1  91.44,82.3 0 top
X2  10.92,3.3 0 top

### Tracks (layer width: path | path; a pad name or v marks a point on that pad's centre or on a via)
9V-10V  (via drill 0.3 pad 0.61)
  TOP 0.381: 65.28,75.83 C21.1 67.31,75.83 | 53.72,73.91 53.85,73.79 C25.1 | U10.2 48.17,16.34 v48.01,16.51 | U10.3 48.82,16.31 v49.02,16.51
  TOP 0.508: v65.28,74.68 65.28,75.83 | v69.22,73.28 U12.5 | v51.69,73.28 U13.8 | v52.83,73.91 53.72,73.91 | v73.03,73.28 U12.8 | v74.04,74.93 74.42,74.93 C22.1 | v37.72,73.28 U14.5 | v41.53,73.28 U14.8 | C28.1 v43.69,74.04 | v47.88,73.28 U13.5 | C21.1 v66.29,74.68 | 67.31,75.83 v67.31,74.68 | v29.85,73.15 U16.8 | C51.1 31.55,73.71 v30.99,73.15 | v26.04,73.15 U16.5 | U5.4 41.34,19.49 41.4,19.81 v41.4,18.29 | C41.2 43.43,18.8 42.93,18.8 v42.42,18.29 | C11.2 v45.47,16.26
  pour BOTTOM: 0.64,61.72 0.64,77.47 75.69,77.47 75.69,61.72
  pour PWR PLANE: 0.64,77.47 16.26,77.47 16.26,18.8 50.04,18.8 50.04,0.63 0.64,0.63
+1.8V  (via drill 0.3 pad 0.61)
  TOP 0.254: C38.1 75.18,54.36 U11.13 v75.18,51.05 | v75.18,34.92 U11.63 v75.18,37.85 | C37.1 75.69,34.42
  TOP 0.508: C23.1 v71.88,82.55 | v72.9,82.55 C24.1 | U12.2 v71.76,81.53 | U12.1 v73.03,81.53 | 75.18,54.36 v75.82,54.36 | 75.69,34.42 v75.18,34.92
  pour PWR PLANE (no thermals): 76.45,93.34 64.26,93.34 64.26,57.91 73.41,48.77 73.41,33.78 76.45,33.78
+2.5V  (via drill 0.3 pad 0.61)  (14 unrouted)
  TOP 0.254: U1.2 55.12,34.04 55.12,34.29 55.37,34.29 55.12,34.39 v55.12,35.56
  TOP 0.381: U14.1 41.53,80.77
  TOP 0.508: 41.53,80.77 v41.53,81.66 | C30.1 v40.89,82.55 | C29.1 43.69,79.76 v42.93,79.76 | U14.2 v40.26,81.66 | C10.2 v54.61,36.32 | C9.2 52.58,37.34 v53.59,37.34 | JP2.1 34.6,18.74 C8.2 39.06,18.74 39.44,19.12 U5.6
  other vias: 55.12,34.54 53.59,36.32 54.1,35.56 54.1,34.54 52.83,35.56 52.83,34.54
  pour PWR PLANE: 37.85,93.34 45.72,93.34 45.72,49.53 53.34,49.53 58.93,43.94 58.93,31.5 50.55,31.5 50.55,41.15 49.02,42.67 37.85,42.67
  pour TOP: 52.07,37.59 55.5,37.59 55.5,33.53 52.07,33.53
+3.3V  (via drill 0.3 pad 0.61)
  TOP 0.254: U11.9 77.18,53.31 77.47,53.59 77.69,53.63 v77.72,53.59 | U3.8 29.98,51.69 29.97,51.69 | 65.52,41.16 C34.1 65.73,40.95 U11.45 68.64,40.95 v68.83,41.15 | 71.89,34.28 v71.88,34.29 | U11.59 73.18,35.72 72.64,35.18 | 85.22,41.27 C32.1 84.84,41.27 84.01,40.45 U11.80 81.72,40.45 v81.53,40.64 | v81.53,47.75 81.84,47.45 U11.94 84.03,47.45 84.84,48.26 C31.1 | U3.6 30.98,50.55 v31.37,50.16 | v68.83,48.26 68.52,47.95 U11.31 66.35,47.95 66.29,48.01 66.29,48.51 66.04,48.77 C35.1 | 61.72,37.08 61.67,37.14 | U1.15 60.2,34.04 v59.69,34.54
  TOP 0.381: C27.1 v52.32,82.55 | R2.2 20.32,59.18 | C1.1 23.62,58.42 | U8.5 23.64,56.53 23.62,56.51 v23.62,57.15 | C2.1 29.08,58.42 | U2.5 29.23,56.53 29.21,56.51 v29.21,57.15 | 29.97,51.69 v29.97,52.07 | 51.42,50.69 v51.31,50.8 | C13.1 51.31,51.56 | U9.5 56.02,48.4 | C15.2 57.91,48.51 | C4.1 64.77,53.85 | U4.5 64.88,55.74 v63.75,55.75 | 64.78,48.76 v64.77,48.77 | v85.84,48.25 v85.85,48.26 | R21.1 77.47,11.94 v77.47,12.7 | v65.53,35.05 R30.1
  TOP 0.508: C36.1 v77.72,54.61 v77.72,53.59 | U13.1 v51.69,81.66 | 20.32,59.18 21.34,60.2 v21.59,60.2 | 23.62,58.42 v23.62,59.18 | 29.08,58.42 v29.08,59.18 | C3.1 v29.97,53.34 | U6.5 51.42,50.69 | 51.31,51.56 v51.31,52.32 | 56.02,48.4 56.01,48.39 56.01,47.75 v57.15,47.75 | v57.15,48.77 57.91,48.77 C15.2 | 65.52,41.16 65.53,41.78 v65.66,41.91 | 71.89,34.28 C33.1 72.64,35.18 v72.39,35.18 | 85.22,41.27 v85.85,41.27 | 64.77,53.85 v64.77,54.61 | C35.1 64.78,48.76 | C31.1 v85.84,48.25 | R25.2 53.85,81.03 v53.09,81.03 | C26.1 53.85,82.55 v53.85,81.79 | v60.96,36.45 60.96,36.83 61.21,37.08 61.72,37.08 C7.2 | C6.2 v59.69,36.32
  other vias: 50.29,52.32 50.29,50.8 60.71,37.46 60.45,35.56
  pour PWR PLANE (no thermals): 93.35,0.63 50.55,0.63 50.55,30.99 59.44,30.99 59.44,44.2 53.59,50.04 46.23,50.04 46.23,93.34 63.75,93.34 63.75,57.66 72.9,48.51 72.9,33.27 76.96,33.27 76.96,93.34 93.35,93.34
  pour BOTTOM: 19.81,60.96 19.81,46.48 52.58,46.48 52.58,60.96
  pour TOP: 59.31,37.72 59.31,33.78 62.36,33.78 62.36,37.72
-9V/-10V  (via drill 0.3 pad 0.61)
  TOP 0.508: v14.73,79.25 U17.2 | U17.3 15.69,78.29 15.75,78.23 v14.73,78.23 | v12.7,78.23 12.7,78.74 | C54.1 13.72,78.74 12.7,78.74 | 12.7,78.74 v12.7,79.25
  pour PWR PLANE: 0.64,93.34 16.26,93.34 16.26,77.98 0.64,77.98
BUSY
  TOP 0.254: U11.36 65.52,45.45 64.77,44.7 64.77,34.8 65.28,34.29 66.8,34.29 67.31,33.78 67.31,32.26 66.8,31.75 66.04,31.75 | 66.04,31.75 BUSY.1 | U1.11 63.25,32 63.5,31.75 66.04,31.75
CLK
  TOP 0.254: U11.12 75.68,53.33 75.95,53.59 76.2,53.59 76.71,54.1 76.71,55.63 74.42,57.91 32.77,57.91 31.19,56.34 R3.2 31.24,56.39
CLKOUT
  TOP 0.254: U11.6 78.68,57.86 89.41,68.58 J2.3
CNV  (via drill 0.3 pad 0.61)
  TOP 0.254: U6.2 52.07,48.26 | 51.05,5.33 51.05,5.05 J3.6 | 61.21,30.87 U1.9
  TOP 0.381: 52.07,46.99 U6.2 | 61.21,30.73 61.21,30.87
  TOP 0.762: 61.21,30.73 61.98,29.97 v63.5,29.97 v63.5,30.99 | CNV.1 63.25,19.56 63.25,8.38 61.47,6.6 52.32,6.6 51.05,5.33 | v62.23,46.23 v61.21,46.23 52.83,46.23 52.07,46.99 52.32,46.74
  BOTTOM 0.762: CNV.1 62.99,22.86 62.99,29.46 v63.5,29.97 63.5,44.96 v62.23,46.23 v61.21,46.23
CNVST_33
  TOP 0.254: U11.15 74.18,53.2 73.91,53.47 70.1,53.47 67.18,56.39 U4.2 66.29,56.39
DB0
  TOP 0.254: U11.73 80.18,34.62 84.84,29.97 86.11,29.97 87.12,28.96 87.12,27.43 89.15,25.4 J2.37
DB1
  TOP 0.254: U11.74 80.68,35.14 85.09,30.73 86.36,30.73 89.15,27.94 J2.35
DB2
  TOP 0.254: U11.75 81.18,35.66 85.34,31.5 88.39,31.5 89.41,30.48 J2.33
DB3
  TOP 0.254: U11.76 83.72,38.45 89.15,33.02 J2.31
DB4
  TOP 0.254: U11.77 85.76,38.95 89.15,35.56 J2.29
DB5
  TOP 0.254: U11.78 88.06,39.45 89.41,38.1 J2.27
DB6
  TOP 0.254: U11.84 87.34,42.45 89.15,40.64 J2.25
DB7
  TOP 0.254: U11.89 87.37,44.95 87.38,44.96 89.15,43.18 J2.23
DB8
  TOP 0.254: U11.92 88.68,46.45 89.41,45.72 J2.21
DB9
  TOP 0.254: U11.96 84.01,48.45 84.84,49.28 88.39,49.28 89.22,48.45 91.44,48.45 J2.19
DB10
  TOP 0.254: U11.100 91.44,50.45 J2.17
DB11
  TOP 0.254: U11.1 81.18,52.99 81.53,53.34 J2.15
DB12
  TOP 0.254: U11.2 80.68,53.51 83.06,55.88 J2.13
DB13
  TOP 0.254: U11.3 80.18,54.02 84.58,58.42 J2.11
DB14
  TOP 0.254: U11.4 79.68,54.54 86.11,60.96 J2.9
DB15
  TOP 0.254: U11.5 79.18,55.05 87.63,63.5 J2.7
DB16
  TOP 0.254: U11.71 79.18,31.05 DB16.1
  BOTTOM 0.254: J2.38 86.36,25.4 DB16.1
DB17
  TOP 0.254: U11.72 79.68,33.85 DB17.1
  BOTTOM 0.254: DB17.1 J2.36
DC590_DETECT
  TOP 0.254: U6.4 52.72,49.64 53.48,49.64 54.61,48.51 54.74,48.51 54.74,48.17 U9.4 54.72,48.15 54.74,48.13 54.74,47.75 55.5,46.99 61.47,46.99 64.93,50.45 U11.26
DC590VP  (via drill 0.3 pad 0.61)
  TOP 0.254: C16.1 57.91,53.09 57.86,53.03 | 56.19,53.09 R13.2 56.13,53.09 56.19,53.09
  TOP 0.762: R13.2 57.86,53.03 | v56.13,53.85 56.13,53.09
  BOTTOM 0.254: J3.2 46.99,5.33
  BOTTOM 0.762: v56.13,53.85 56.13,30.23 51.31,25.4 51.31,9.65 46.99,5.33
GND  (via drill 0.3 pad 0.61, 0.51 pad 1.02)
  TOP 0.254: U11.65 76.18,37.83 v76.2,37.85 | U11.60 73.68,37.69 v73.91,37.85 | U3.2 25.78,51.05 v25.65,51.05 | U3.4 v25.64,50.05 v25.65,50.04 | U8.3 22.1,55.23 | R6.1 20.32,52.58 | U9.3 54.72,50.18 54.61,50.29 | U6.3 52.74,48.17 52.71,48.13 52.83,47.88 | C34.2 65.54,40.14 | v68.83,40.13 68.52,40.45 U11.46 66.36,40.45 66.04,40.13 C34.2 | 73.4,33.28 v73.41,33.27 | 74.92,33.28 v74.93,33.27 | 76.44,33.28 v76.45,33.27 | 77.97,33.28 v77.98,33.27 | v85.84,40.27 v85.85,40.26 | 76.68,50.82 76.69,50.82 76.69,50.78 v76.71,50.8 | 76.68,50.82 76.48,50.82 76.45,50.8 76.2,51.05 U11.11 | 76.68,50.82 U11.10 | 76.68,50.82 v76.71,49.78 | v68.83,47.24 68.63,47.45 U11.32 65.74,47.45 C35.2 | v81.53,39.62 81.86,39.95 U11.79 84.91,39.95 85.09,40.13 C32.2 | v81.53,46.74 81.75,46.95 U11.93 84.8,46.95 C31.2 | 58.17,31.79 57.91,32 U1.6 55.25,32 55.03,31.79 | 58.17,33.53 U1.3 | U1.16 61.21,34.66 | U1.10 62.48,31.5 v62.48,31.24
  TOP 0.381: U13.3 49.15,79.76 | 53.85,75.44 C25.2 | 65.28,79.25 66.04,79.11 C21.2 66.29,79.25 67.31,79.25 | C2.2 27.69,58.42 | C1.2 22.1,58.42 | U2.3 27.57,55.23 27.56,55.24 v27.56,54.61 | 22.1,55.23 v22.1,54.36 | C18.2 16.26,40.13 | 53.29,51.51 v53.34,51.56 | C15.1 57.91,50.04 | 54.61,50.29 v54.1,50.29 | C36.2 | C24.2 75.18,82.55 | 74.3,76.83 v74.17,76.83 | C22.2 74.68,76.45 | v82.8,78.99 82.88,78.92 | 82.3,78.99 82.23,78.92 | v81.79,78.99 81.53,78.99 81.58,78.95 | 83.31,78.99 83.53,78.95 | v74.8,56.13 75.18,55.75 C38.2 | C4.2 66.29,53.85 | U4.3 67.71,57.04 v67.69,57.02 | 85.84,47.25 v85.85,47.24 | C28.2 43.49,76.4 43.43,76.45 | v42.93,78.23 42.98,78.28 | 64.78,47.76 v64.77,47.75 | C39.2 51.44,35.05 | R24.2 v74.42,11.94 | v67.06,35.05 R44.2 | v58.17,31.75 58.17,31.79 | 58.17,33.53 58.17,33.74 | 61.21,34.66 61.47,34.67 61.98,34.67 v62.1,34.8 | v62.48,31.24 62.48,31.39 | 55.03,31.79 v54.99,31.75 | U10.4 49.47,15.69 v50.04,16.26 | U10.8 47.52,21.31 v47.5,21.34 | U10.5 49.47,21.28 v49.53,21.34 | U10.7 48.17,21 v48.51,21.34
  TOP 0.508: v70.49,78.49 U12.3 | U12.7 v71.76,76.45 | U12.6 v70.49,76.45 | v49.15,78.61 U13.3 | U13.6 v49.15,76.45 | U13.7 v50.42,76.45 | v52.83,75.44 53.85,75.44 | v65.28,80.26 65.28,79.25 | v38.99,78.49 U14.3 | 27.69,58.42 v27.69,59.18 | 22.1,58.42 v22.1,59.18 | C3.2 v26.92,53.34 | 20.32,52.58 v20.32,51.82 | 16.26,40.13 v16.26,39.37 | C13.2 52.58,51.43 52.65,51.51 53.29,51.51 | R17.1 54.36,53.09 v53.72,53.09 | 57.91,50.04 v57.15,50.04 | C16.2 57.91,51.56 v57.15,51.56 | 52.83,47.88 v53.34,47.88 | 65.54,40.14 65.53,39.37 v65.66,39.24 | C33.2 73.4,33.28 | R22.1 74.92,33.28 | C37.2 76.44,33.28 | R23.1 77.97,33.28 | C32.2 v85.84,40.27 | C36.2 v77.22,56.9 | 75.18,82.55 v75.18,81.53 | 74.68,76.45 74.3,76.83 | 82.88,78.92 U7.2 | v81.79,78.99 82.3,78.99 v82.8,78.99 83.31,78.99 v83.82,78.99 | 82.23,78.92 U7.3 | v80.77,78.99 81.53,78.99 | 81.58,78.95 U7.4 | 83.53,78.95 U7.1 | C14.2 v85.6,76.45 | R20.1 v73.66,56.13 | 66.29,53.85 v66.29,54.61 | C31.2 85.84,47.25 | U14.7 v40.26,76.45 | U14.6 v38.99,76.45 | v42.93,76.45 43.43,76.45 | 42.98,78.28 C29.2 | R5.1 16.76,59.18 v15.49,59.18 | C35.2 64.78,47.76 | R27.1 v62.74,78.23 | C21.2 v66.29,80.26 | 67.31,79.25 v67.31,80.26 | C42.2 23.88,40.18 v23.88,39.37 | R15.2 19.3,40.18 v19.3,39.37 | C49.2 23.88,20.27 v23.88,21.08 | R41.2 arc90 19.3,20.27 v19.3,21.08 | C47.2 arc-90 16.26,22.4 v16.26,21.59 | R37.1 25.4,24.64 v25.4,23.88 | C39.2 v51.44,35.94 | C12.1 51.56,17.27 v52.32,17.27 | C11.1 v45.47,19.56 | C8.1 v37.34,16.51 | U5.1 39.44,16.58 39.37,16.51 v39.37,15.24 | U5.2 v40.39,15.24 | C41.1 v43.43,16.51 | C46.1 v36.32,10.41 | R7.2 56.64,38.61 v57.4,38.61 | 54.61,38.61 55.12,39.12 v55.12,39.37 | 52.58,38.61 v52.58,39.37 | v58.93,38.61 59.69,38.61 C6.1 v59.69,39.37
  TOP 0.508: v60.96,38.61 61.72,38.61 C7.1 v61.72,39.37 | U16.6 v27.31,76.45 | U16.7 v28.58,76.45 | v27.31,78.49 U16.3 | R29.1 v22.35,81.03 | R43.1 31.75,76.71 v30.99,76.71 | C51.2 31.75,75.18 v30.99,75.18 | C52.2 33.27,82.55 v33.27,81.79 | C53.2 v15.49,82.55 | C54.2 v13.72,81.03 | U17.1 15.75,80.26 15.49,80.26 v15.49,81.03 | C26.2 55.37,82.55 v55.37,81.79 | R26.1 53.65,76.76 53.59,76.71 v52.83,76.71 | C9.1 52.58,38.61 | 52.58,38.61 v53.34,38.61 | C10.1 54.61,38.61 | 54.61,38.61 54.1,39.12 v54.1,39.37 | C56.1 53.59,29.46 v53.59,30.23 | v40.13,40.13 C43.2 | C61.2 26.87,37.39 v26.92,37.34 | C62.2 26.87,32.21 v26.92,32.26 | C45.1 25.45,25.96 v25.4,25.91 | C63.2 26.87,23.06 v26.92,23.11 | v40.13,41.66 C44.2 | 51.44,30.48 C40.2 v51.44,29.59 | C59.2 v36.58,32.51 | C60.2 v36.58,34.04 | C20.1 51.56,27.81 51.56,28.32 v52.32,29.08
  TOP 1.016: 58.17,33.15 58.17,33.53
  TOP 1.524: v1.27,44.45 v58.17,44.45 v58.17,36.45 58.17,33.53 | 58.17,33.15 v58.17,31.75 v58.17,11.43 v41.91,11.43 v41.91,1.27
  BOTTOM 0.381: 88.9,53.34 90.93,53.34 | 88.9,58.42 90.42,58.42
  BOTTOM 0.406: J2.40 88.39,22.86 v87.88,23.37
  BOTTOM 0.508: v87.88,48.26 J2.20 | v87.88,51.31 88.39,50.8 J2.18 | v87.88,54.36 88.9,53.34 | v87.88,59.44 88.9,58.42 | 90.93,53.34 J2.16 | J2.14 88.65,55.88 v87.88,56.64 | 90.42,58.42 J2.12 | J2.10 88.65,60.96 v87.88,61.72 | J2.8 88.65,63.5 v87.88,64.26 | J2.6 88.14,66.04 v87.88,65.79 | v87.88,30.48 J2.34 v87.88,30.48 | v87.88,33.02 J2.32 v87.88,33.02 | v87.88,35.56 J2.30 v87.88,35.56 | v87.88,38.1 J2.28 v87.88,38.1 | v87.88,40.64 J2.26 v87.88,40.64 | v87.88,43.18 J2.24 v87.88,43.18 | v87.88,45.72 J2.22 v87.88,45.72 | v87.88,68.58 J2.4 v87.88,68.58
  other vias: 43.18,44.45 48.26,44.45 53.34,44.45 33.02,44.45 27.94,44.45 38.1,44.45 58.17,41.15 58.17,29.21 58.17,20.07 58.17,16.26 54.61,11.43 45.72,11.43 41.91,8.13 22.86,44.45 17.78,44.45 12.7,44.45 8.89,44.45 50.04,11.43 41.91,4.83 58.17,34.16 58.17,26.67
  pour GND PLANE: 0.64,0.63 0.64,93.34 93.35,93.34 93.35,0.63
N$1
  TOP 0.254: R14.1 17.78,38.1 17.73,38.15
  TOP 0.508: 19.3,38.1 17.78,38.1 | 19.3,38.1 C17.1 | 17.73,38.15 C18.1 | JP1.2 19.3,34.8 19.3,38.1
N$2
  TOP 0.254: 16.26,38.1 16.26,37.85
  TOP 0.381: 16.26,38.1 R14.2
  TOP 0.508: J4.1 16.26,38.1
N$3  (via drill 0.3 pad 0.61)
  TOP 0.254: U11.23 70.18,50.47 v71.12,49.53
  BOTTOM 0.254: J5.9 78.74,4.32 78.74,12.7 71.12,20.32 v71.12,49.53
N$4  (via drill 0.3 pad 0.61)
  TOP 0.254: U11.24 69.68,50.89 v68.96,50.16
  TOP 0.381: 71.88,11.94 71.83,11.99 71.93,11.99 R24.1 71.88,11.94 | v71.12,12.7 71.88,11.94
  BOTTOM 0.254: v68.96,50.16 67.82,49.02 67.82,16 v71.12,12.7 71.12,4.32 J5.1
N$5  (via drill 0.3 pad 0.61)
  TOP 0.254: v68.83,51.31 69.18,51.68 69.18,51.91 U11.25
  BOTTOM 0.254: J5.3 73.66,4.32 73.66,12.7 69.6,16.76 69.6,49.28 69.85,49.53 69.85,50.55 69.09,51.31 v68.83,51.31
N$6  (via drill 0.3 pad 0.61)
  TOP 0.254: U11.22 70.68,51.25 v71.12,50.8 | 76.2,12.19 76.2,12.14 R21.2 75.95,11.94 76.2,12.19 | v76.2,12.7 76.2,12.19
  BOTTOM 0.254: v71.12,50.8 70.36,50.04 70.36,18.29 v76.2,12.7 76.2,4.32 J5.5
N$7
  TOP 0.254: U1.7 55.75,31.5 55.07,30.81
  TOP 0.381: 55.04,29.13 55.12,29.21 55.07,29.26 C56.2
  TOP 0.508: C56.2 55.07,30.81 | 55.04,29.13 R46.1 C20.2 53.34,27.94 53.34,23.95 53.42,23.95 JP6.1
  BOTTOM 0.381: 53.54,23.67 JP6.1
  BOTTOM 0.508: JP4.2 54.86,16.51 53.54,17.83 53.54,23.67
N$8  (via drill 0.3 pad 0.61)
  TOP 0.381: C58.1 42.42,28.45 | 42.67,30.35 U15.4 42.62,30.28 42.67,30.23 | R45.1 42.42,26.67 42.37,26.72 | v44.45,34.16 44.5,34.21 | 42.67,31.24 v42.8,31.37
  TOP 0.508: 42.67,30.35 42.74,30.28 42.74,28.77 42.42,28.45 | 42.37,26.72 C58.1 | 44.5,34.21 R32.2 | 42.67,30.23 42.67,31.24
  BOTTOM 0.508: v44.45,34.16 42.8,32.51 v42.8,31.37
N$9
  TOP 0.254: U11.64 75.68,35.69 77.09,34.29 R23.2
N$10
  TOP 0.508: JP4.3 41.91,13.97 35.56,7.62 E6.1
N$11
  TOP 0.254: U1.1 56.5,34.66
  TOP 0.508: 56.5,34.66 56.52,34.67 56.52,36.96 56.64,37.08 R7.1
N$12
  TOP 0.254: U3.3 27.94,50.55 29.46,49.02 29.46,48.26 R8.1
N$13
  TOP 0.254: R13.1 56.13,51.56 56.08,51.61 55.37,51.61 | 55.37,51.61 R17.2 | U9.2 55.37,51.61
N$14
  TOP 0.254: JP3.1 62.74,75.95
  TOP 0.508: 62.74,75.95 R27.2
N$15
  TOP 0.254: 54.41,33.09 54.41,33.08 54.36,33.02 U1.4
  TOP 0.381: 54.41,33.09 53.98,33.53 R16.1
N$16
  TOP 0.254: 54.41,32.44 54.48,32.51 U1.5
  TOP 0.381: R19.1 53.97,32.01 53.98,32 54.41,32.44
N$17
  TOP 0.254: R10.1 83.31,71.88 82.88,72.32 U7.7
N$18
  TOP 0.254: 31.75,78.23 R42.1 | U16.2 28.58,79.12 29.46,78.23 31.75,78.23 | 31.75,78.23 R43.2
N$19  (via drill 0.3 pad 0.61)
  TOP 0.254: U7.6 82.23,71.19 82.8,70.61 v83.31,70.61 83.36,70.56 R11.1 | v86.11,71.12 J2.1
  BOTTOM 0.254: J3.11 57.02,2.92 58.67,1.27 81.53,1.27 83.31,3.05 v83.31,70.61 83.82,71.12 v86.11,71.12
N$20
  TOP 0.254: U17.4 18.54,78.31 18.54,78.23 19.1,78.79 R28.1 22.3,78.79 22.35,78.74 R29.2
N$21
  TOP 0.381: 51.56,18.8 51.61,18.85 | U10.6 48.82,19.25
  TOP 0.508: 51.61,18.85 55.17,18.85 JP4.1 | 48.82,19.25 49.28,18.8 51.56,18.8 C12.2
N$22
  TOP 0.381: C19.1 48.13,34.42 | 51.44,33.53 C39.1 | 45.92,36.78 45.97,36.83 R31.1 | R32.1 45.97,35.05 45.92,35.1 R32.1
  TOP 0.508: 48.13,34.42 49.02,33.53 51.44,33.53 R16.2 | 45.92,35.1 45.92,36.78 | C19.1 47.24,35.05 R32.1
N$23
  TOP 0.254: R4.1 31.75,51.31 31.49,51.05 U3.7
N$24
  TOP 0.381: C46.2 34.04,10.41 34.29,10.67
  TOP 0.508: 34.29,10.67 JP2.3 | C46.2 31.75,10.41 E7.1
N$25
  TOP 0.254: R4.2 33.27,51.31 33.27,51.43 38.86,57.02 64.64,57.02 64.66,57.04 U4.4
N$26
  TOP 0.508: 20.83,40.08 R15.1 | 20.83,38.1 20.83,40.08 | 20.83,38.1 C17.2 | 20.83,38.1 R9.1 | JP1.3 20.83,34.8 20.83,38.1 | 20.83,40.08 20.88,40.13 22.35,40.13 | 22.35,40.13 C42.1 | 22.35,40.13 22.61,40.13 22.61,40.89 23.11,41.4 31.5,41.4 37.34,35.56 R33.2
N$27
  TOP 0.508: 16.76,55.88 C5.1 | 16.76,55.88 R5.2 | J1.1 16.76,55.88
N$28
  TOP 0.254: R2.1 20.07,57.91
  TOP 0.381: 20.32,55.88 C5.2
  TOP 0.508: R6.2 20.32,55.88 | 20.32,55.88 U8.2 22.35,55.88 | 20.32,55.88 R2.1
N$29
  TOP 0.254: U3.1 26.67,51.55 26.67,51.56 25.65,52.58 R1.2
N$30
  TOP 0.254: R22.2 74.17,35.05 74.68,35.57 U11.62
N$31
  TOP 0.254: 31.24,54.86 R3.1 31.24,55.23 U2.4
N$32
  TOP 0.381: C19.2 48.26,31.24 | 51.44,32 C40.1 | R36.1 45.92,30.53 45.97,30.48 | 47.75,31.24 47.82,31.17
  TOP 0.508: 48.26,31.24 49.02,32 51.44,32 R19.2 | R38.2 45.97,30.48 | 47.75,31.24 46.99,30.48 R36.1 | 47.82,31.17 C19.2
N$33
  TOP 0.381: U15.8 40.64,35.17 40.64,35.56 40.54,35.56 | 38.86,35.56 R33.1
  TOP 0.508: 40.54,35.56 38.86,35.56 38.86,41.91 39.62,42.67 45.21,42.67 45.97,41.91 R31.2
N$34  (via drill 0.3 pad 0.61)
  TOP 0.254: U7.5 81.53,74.42 81.53,68.07 81.83,67.78 83.27,67.78 83.31,67.82 R12.1 83.31,67.77 83.31,67.31 v84.07,66.55
  BOTTOM 0.254: J3.9 55.02,2.9 57.15,0.76 82.04,0.76 84.07,2.79 v84.07,66.55 88.65,71.12 J2.2
N$36
  TOP 0.254: U2.2 25.91,55.88 25.65,55.63 | 25.6,55.57 25.27,55.24 23.75,55.24 23.75,55.23
  TOP 0.381: 25.65,55.63 R1.1 25.6,55.57 | U8.4 23.75,55.23
N$37
  TOP 0.381: R18.1 26.92,29.21 | C45.2 26.92,26.92 26.87,26.98 | R37.2 26.92,24.64 26.87,24.69
  TOP 0.508: R34.2 28.7,30.99 26.92,29.21 | 26.87,26.98 R18.1 | 26.87,24.69 C45.2
N$38
  TOP 0.254: 53.85,78.23 R25.1 | U13.2 50.42,79.12 51.31,78.23 53.85,78.23 | 53.85,78.23 R26.2 58.37,78.18 JP3.2
N$39
  TOP 0.254: 56.4,30.87 U1.8
  TOP 0.381: 56.39,30.86 56.4,30.87 | 56.39,27.81 R46.2
  TOP 0.508: JP6.2 56.39,24.38 56.39,27.81 56.39,30.86
N$40
  TOP 0.381: C58.2 40.89,28.45 | 40.51,30.23 U15.1 | R45.2 40.89,26.67 40.95,26.72
  TOP 0.508: 40.51,30.23 40.54,30.2 40.54,28.8 40.89,28.45 | 40.95,26.72 C58.2 | R45.2 40.95,25.86 42.16,24.64 R35.1
N$41
  TOP 0.254: U6.1 51.44,48.17 51.44,48.26 R8.2
N$42
  TOP 0.508: J8.1 R39.2
N$43  (via drill 0.3 pad 0.61)
  TOP 0.381: 42.67,35.13 U15.5 | R36.2 44.45,30.48
  TOP 0.508: 42.67,35.13 42.67,34.37 v42.8,34.16 44.45,32.51 v44.45,31.37 44.45,30.48
N$44
  TOP 0.381: 41.19,31.33 41.15,31.5 41.32,31.33 U15.2
  TOP 0.508: 41.19,31.33 41.02,31.5 39.37,31.5 R34.1
N$45  (via drill 0.3 pad 0.61)
  TOP 0.254: 84.84,69.85 R11.2 84.78,71.83 | 84.84,67.82 84.84,69.85 | 84.84,69.85 84.78,69.8 | 84.78,71.83 84.84,71.88 | v82.55,22.1 88.39,22.1 88.9,22.61 88.9,22.86 J2.39 | 84.78,71.83 84.78,71.93 84.84,71.88 | 84.84,71.88 R10.2 | 84.84,71.88 84.84,74.17 C14.1 85.6,74.17 83.57,74.17 83.51,74.22 83.57,74.42 U7.8 | 84.84,67.82 R12.2 | v82.3,68.83 84.84,68.83 84.84,67.82
  BOTTOM 0.254: v82.3,68.83 82.55,68.58 v82.55,22.1 82.55,3.3 81.03,1.78 64.26,1.78 59.69,6.35 56.13,6.35 55.02,5.23 J3.10
N$48
  TOP 0.508: C48.2 20.83,22.4 20.83,25.91 JP5.3 | C48.2 20.83,22.3 20.83,20.32 R41.1 22.35,20.32 | C48.2 R40.1 | 22.35,20.32 C49.1 | 22.35,20.32 22.35,19.3 22.86,18.8 26.16,18.8 30.73,23.37 45.21,23.37 45.97,24.13 45.97,24.64 | 45.97,24.64 R38.1 | 45.97,24.64 R35.2
N$49
  TOP 0.508: JP5.2 19.3,25.91 19.3,22.4 C48.1 C47.1 17.78,22.3 17.78,20.32 R39.1
N$50
  TOP 0.381: U13.4 47.88,81.91 48.51,82.55 C27.2
N$51
  TOP 0.254: U11.14 74.68,53.59 73.91,54.36 73.66,54.36 R20.2
N$52
  TOP 0.254: U11.50 67.06,38.45 R44.1 R30.2
N$53
  TOP 0.254: U12.4 69.22,82.17 69.6,82.55
  TOP 0.381: 69.6,82.55 C23.2
N$54
  TOP 0.254: C50.2 27.56,82.55 26.04,81.03 26.04,80.14 25.91,80.01 25.91,80.07 U16.4
N$57
  TOP 0.254: C30.2 38.61,82.55 37.72,81.66 U14.4
RD
  TOP 0.254: U11.35 65,45.95 64.26,45.21 64.26,34.54 65.79,33.02 RD.1 65.28,32.26 63.75,32.26 63.5,32.51 U1.12
SCK  (via drill 0.3 pad 0.61)
  TOP 0.254: U11.34 64.48,46.45 63.75,45.72 63.75,33.02 v64.52,33.02 U1.13 | SCK.1 64.52,24.89 62.23,22.61 62.23,8.64 61.09,7.49 51.44,7.49 49.02,5.08 49.02,5.05 J3.4
  BOTTOM 0.254: SCK.1 64.52,25.15 v64.52,33.02
SDO  (via drill 0.3 pad 0.61)
  TOP 0.254: J3.5 51.05,3.05 52.32,1.78 61.21,1.78 64.72,5.28 64.72,17.22 SDO.1 | U11.33 63.97,46.95 63.25,46.23 63.25,34.54 v62.48,33.78 | v62.48,33.78 62.44,33.74 | U1.14 62.23,33.53 v62.48,33.78
  BOTTOM 0.254: SDO.1 61.47,20.57 61.47,32.77 v62.48,33.78
V+  (via drill 0.3 pad 0.61)
  TOP 0.381: U15.3 41.97,32.2 | C55.2 40.89,37.08 41.32,36.66 U15.7 41.32,34.2 v41.15,34.04
  TOP 0.508: C50.1 v30.48,82.55 | U16.1 v29.85,81.66 | R42.2 31.75,81.03 v30.99,81.03 | C52.1 31.75,82.55 v31.75,81.79 | 41.97,32.2 41.66,32.51 v41.02,32.51 | v40.13,38.61 C57.2 | 40.89,37.08 v40.13,37.08 | C60.1 v39.75,34.04 | C59.1 v39.75,32.51
  pour PWR PLANE: 26.16,93.34 37.34,93.34 37.34,42.16 41.4,42.16 41.4,29.46 26.16,29.46
V-  (via drill 0.3 pad 0.61)
  TOP 0.381: C55.1 42.42,37.08 41.97,36.63 U15.6
  TOP 0.508: C53.1 v18.54,82.55 | U17.5 18.47,80.19 18.54,80.26 v18.54,81.03 | R28.2 v20.32,81.03 | C55.1 v43.18,37.08 | C57.1 v43.18,38.61 | C43.1 v43.18,40.13 | C44.1 v43.18,41.66
  pour PWR PLANE: 16.76,93.34 25.65,93.34 25.65,28.96 41.91,28.96 41.91,36.32 41.91,42.16 48.77,42.16 50.04,40.89 50.04,19.3 16.76,19.3
VCMX2  (via drill 0.3 pad 0.61)
  TOP 0.508: R40.2 23.88,22.35 | 23.88,38.05 R9.2 | 23.88,22.35 23.88,29.21 | 23.88,29.21 23.88,31.5 | 23.88,31.5 23.88,38.05 | 23.88,22.35 C63.1 25.45,21.64 v25.4,21.59 | 23.88,31.5 C62.1 | 23.88,29.21 R18.2 | C61.1 25.4,38.1 25.35,38.05 23.88,38.05
  BOTTOM 0.508: v25.4,21.59 30.48,16.51 JP2.2

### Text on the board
BOTTOM: REV 3
tPlace-Top Comp. Outline: V- | V+ | +2.5V | +3.3V | +1.8V | -9V/-10V | VCCIO | 2.5V | GND | 3.3V | 9V-10V | LTC23 | CMS- | LOW POWER, LOW NOISE ADC, | MSPS, | -BIT | DEMO CIRCUIT 1571A- | CLK IN | 100MHz MAX | 3.3Vpp | AC | DC | AIN+ | COUPLING | 0-VREF | COUPLING | AC | DC | FS | CM | VREF | 0.8VREF | (408)432-1900 | VREF/2 | 6652 | www.linear.com | LTC CONFIDENTIAL- | REF | FOR CUSTOMER USE ONLY | AIN- | EXT | EXT | 0-VREF | DC590 | JTAG | EXT_CM | EXT_REF
FAB DWG: NOTES: UNLESS OTHERWISE SPECIFIED | 3.70" | 1. FAB PER IPC-A-600. | 2. MATERIAL: | EPOXY FIBERGLASS, NEMA GRADE FR-4 | FINISHED THICKNESS TO BE 0.062" +/-0.005" | 4-LAYER BOARD, 2 OZ. CU ON OUTER LAYERS, | 1 OZ. CU ON INNER LAYERS, | FLAMMABILITY RATING: 94 V-2 MINIMUM. | 3. SIZE: | CUT TO DIMENSIONS AND TOLERANCES SHOWN. | 0.00" ARE PRIMARY DATUMS. | 4. FINISH: | SMOBC USING LPI BOTH SIDES, COLOR GREEN. | GOLD IMMERSION. LEAD FREE SOLDER CAN BE USED | FOR PROTOTYPE BOARDS. | SILKSCREEN: WHITE NON-CONDUCTIVE EPOXY INK. | 5. DRILL: | PLATE THRU ALL HOLES WITH COPPER, 0.001" THICK MIN. | ALL HOLES SHALL BE DRILLED +/-0.003" WITH | RESPECT TO CTR. OF DRILLED PAD. | ALL HOLES FINISHED SIZE AFTER PLATING. | 6. DROP ALL UNUSED PADS ON INNER LAYERS. | 7. DO NOT ALTER ARTWORK e.g. TO ADD LOGO OR DATE CODE. | PAD SIZE CAN BE MODIFIED TO MEET END FINISH. | 8. PCBS ARE TO BE RoHS COMPLIANT. | 9. SCORING FOR PANELIZED PCB: | 0.017" | 0.02" | XXXXXXXXXXXX | |||||||||||||||||||||||||||||||||||||||||||||||||||||||||||||||||||||||||||||| | XXXXXXXXXXXX | DRILL TABLE | SYM | SIZE | TOL. | QTY | PLATED | 0.00" | 0.188 in | +/-0.003 in | 4 | YES | 0.094 in | +/-0.003 in | 2 | YES | 0.00" | 0.070 in | +/-0.003 in | 2 | NO | 3.70" | 0.064 in | +/-0.003 in | 3 | YES | 0.055 in | +/-0.003 in | 10 | YES | 0.040 in | +/-0.003 in | 23 | YES | 0.035 in | +/-0.003 in | 46 | YES | 0.012 in | +/-0.003 in | 176 | YES | FAB DWG | 3 | 1 | 1
Document: - | 3 | PRODUCTION | GUY H. | 06-25-10 | KT | GUY H. | LOW POWER, LOW NOISE ADC | LTC23XXCMS FAMILY | DEMO CIRCUIT 1571A
Reference: LOW POWER, LOW NOISE ADC | 1571A | 3
tDocu-TOP ASSY DWG: NOTES: UNLESS OTHERWISE SPECIFIED | 1. WORKMANSHIP SHALL BE IN ACCORDANCE WITH IPC-A-610. | 2. INSTALL SHUNTS ON JUMPERS AS SHOWN. | 3. PARTS TO OMIT WILL BE SPECIFIED ON THE BILL OF MATERIALS. | MASK THE SOLDER STENCIL WHERE SMT PARTS ARE OMITTED. | 4. DEPANELIZE BOARDS AFTER ASSEMBLY AND ROUTE-OUT | THE BREAKOUT TABS ON 4 SIDES OF THE BOARD EDGE. | 5. ASSY PROCESS SHALL INCLUDE: REFLOW SOLDER TOP SIDE SMD. | 6. INSTALL 4 STANDOFFS AT 4 CORNERS FROM THE BOTTOM SIDE. | 7. DO NOT APPLY ANY KIND OF ASSEMBLY STAMP OR QA STAMP | ON ANY BOARD. | 8. MARK LTC PART NUMBER AND ASSY VERSION (SEE TABLE) | WITH BLACK PERMANENT MARKER, APPROX. WHERE SHOWN. | ASSY | U1 | MSPS | BIT | -A | LTC2383CMS-16 | 1 | 16 | -B | LTC2382CMS-16 | 0.5 | 16 | -C | LTC2381CMS-16 | 0.25 | 16 | 9. CONNECT JP2 PIN 1 TO E5 BY 3" 24 GAUGE WIRE (WURTH, WE2403-5) | ON THE BACK SIDE OF THE BOARD AS SHOWN ON "DC1571A3-REWORK.PDF". | ASSY DWG | 3 | 1 | 1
